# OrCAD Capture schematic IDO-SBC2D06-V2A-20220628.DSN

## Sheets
1 P01 NOTE: title: IDO-SBC2D06-V1; note: NOTE
2 P02 POWER TREE: note: POWER TREE
3 P03 BLOCK: note: BLOCK
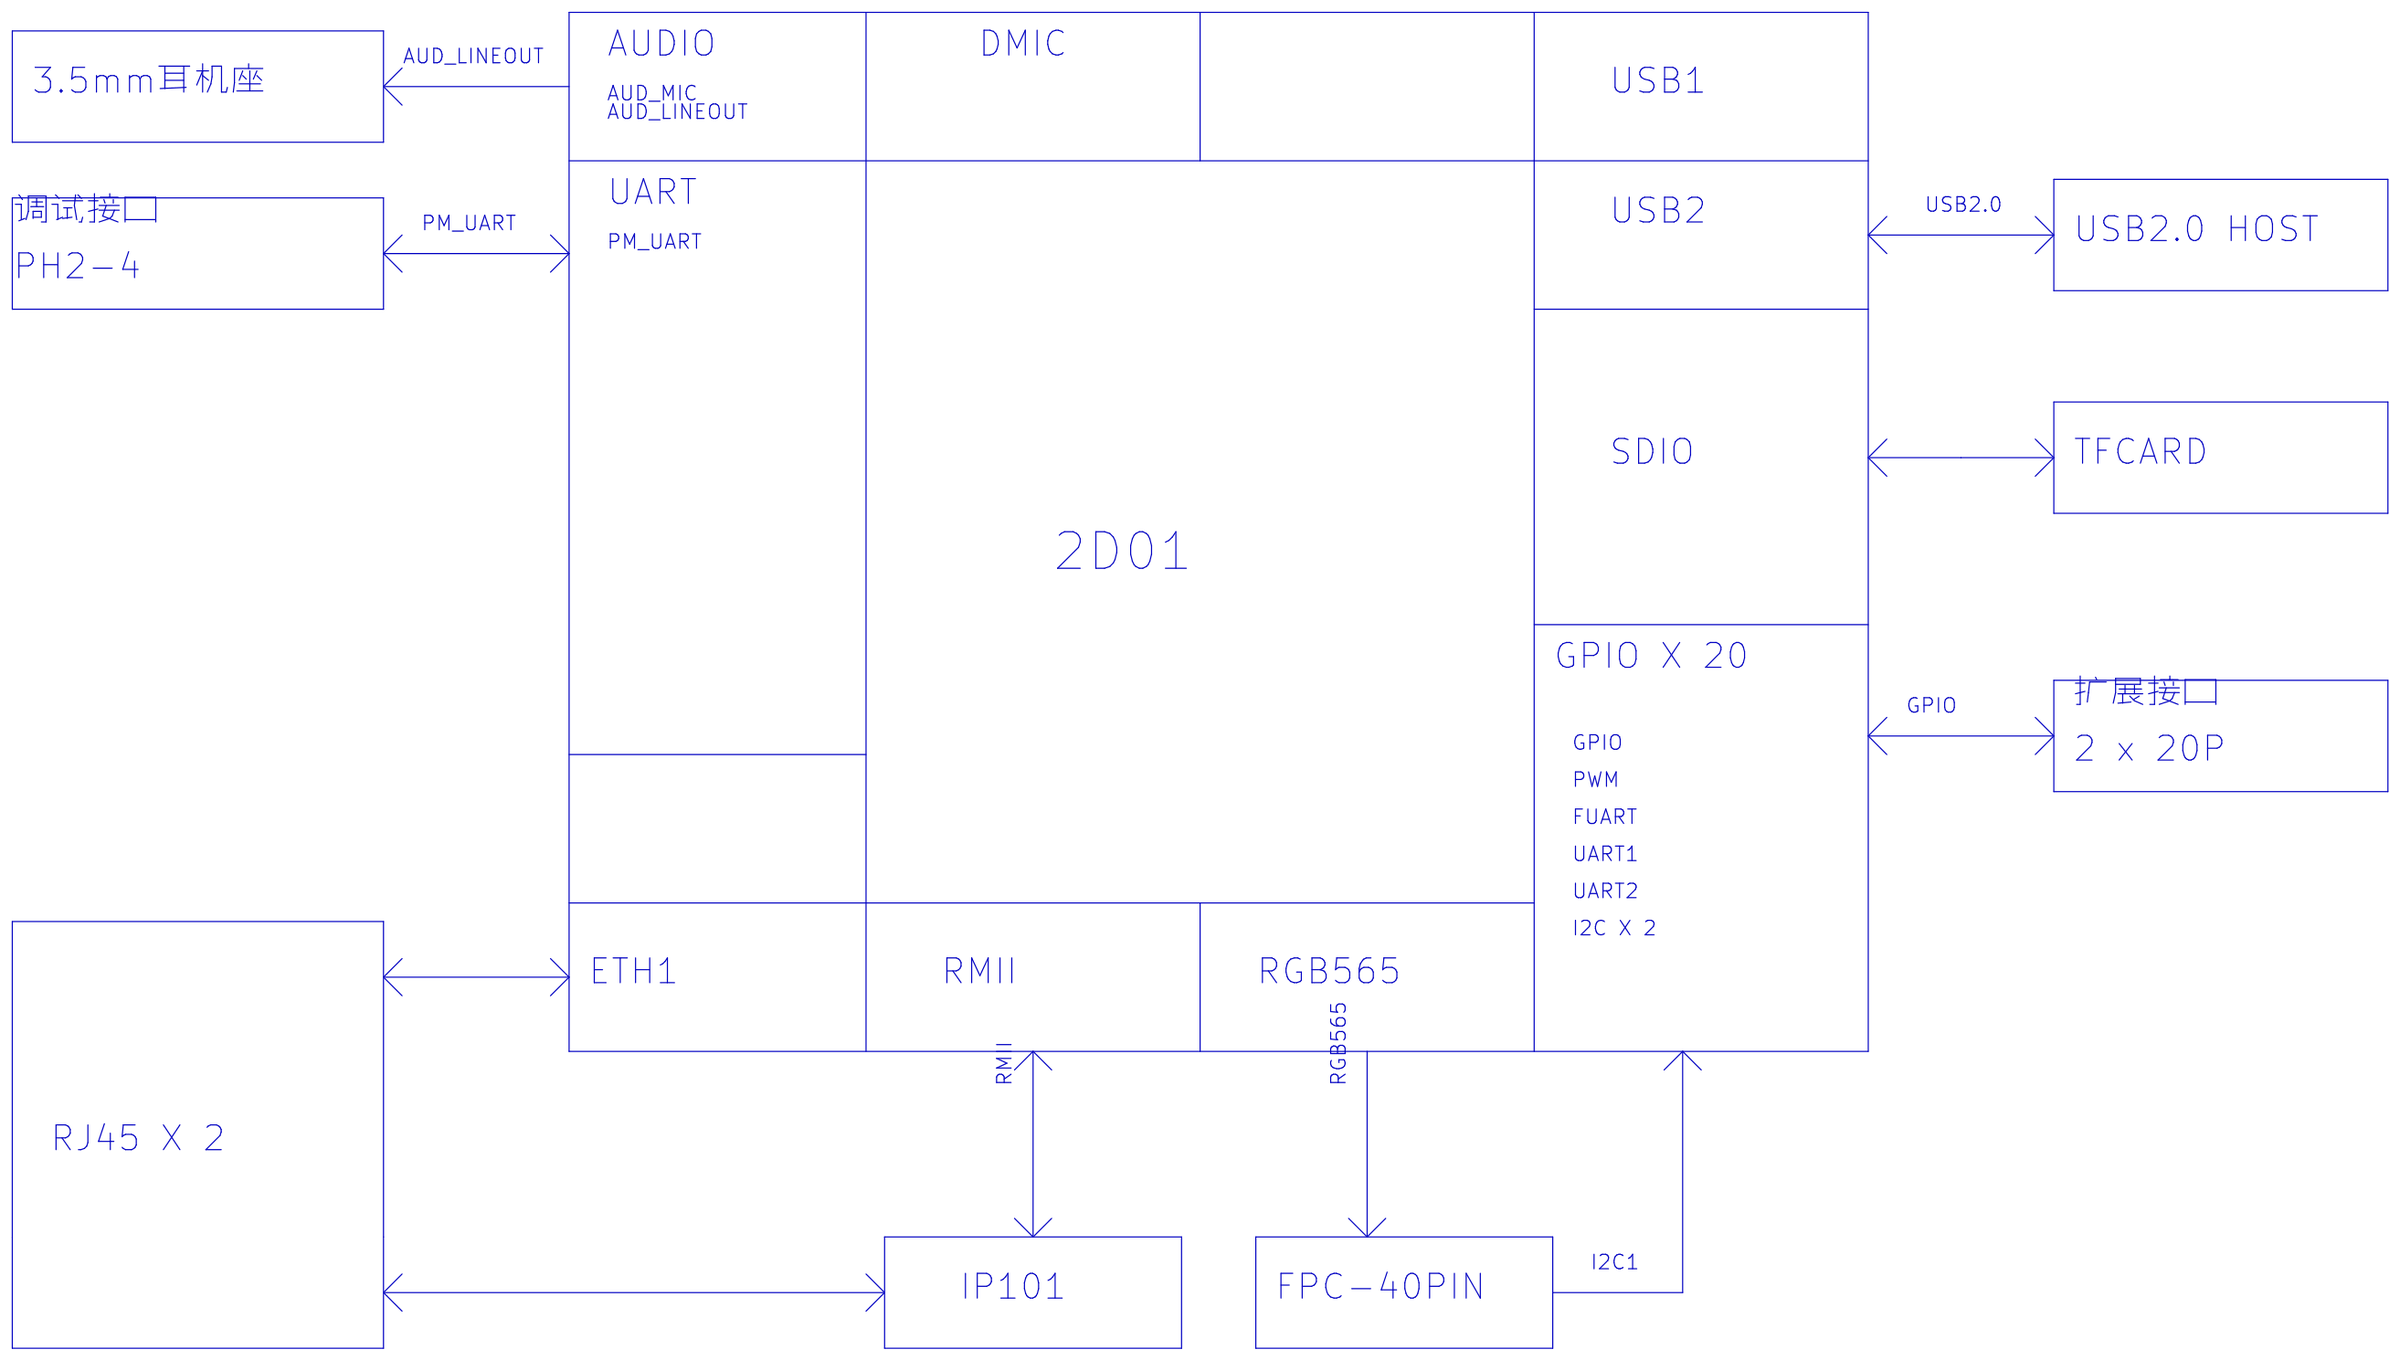
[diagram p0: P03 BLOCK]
4 P04 POWER_SUPPLY: size A3; note: POWER_SUPPLY
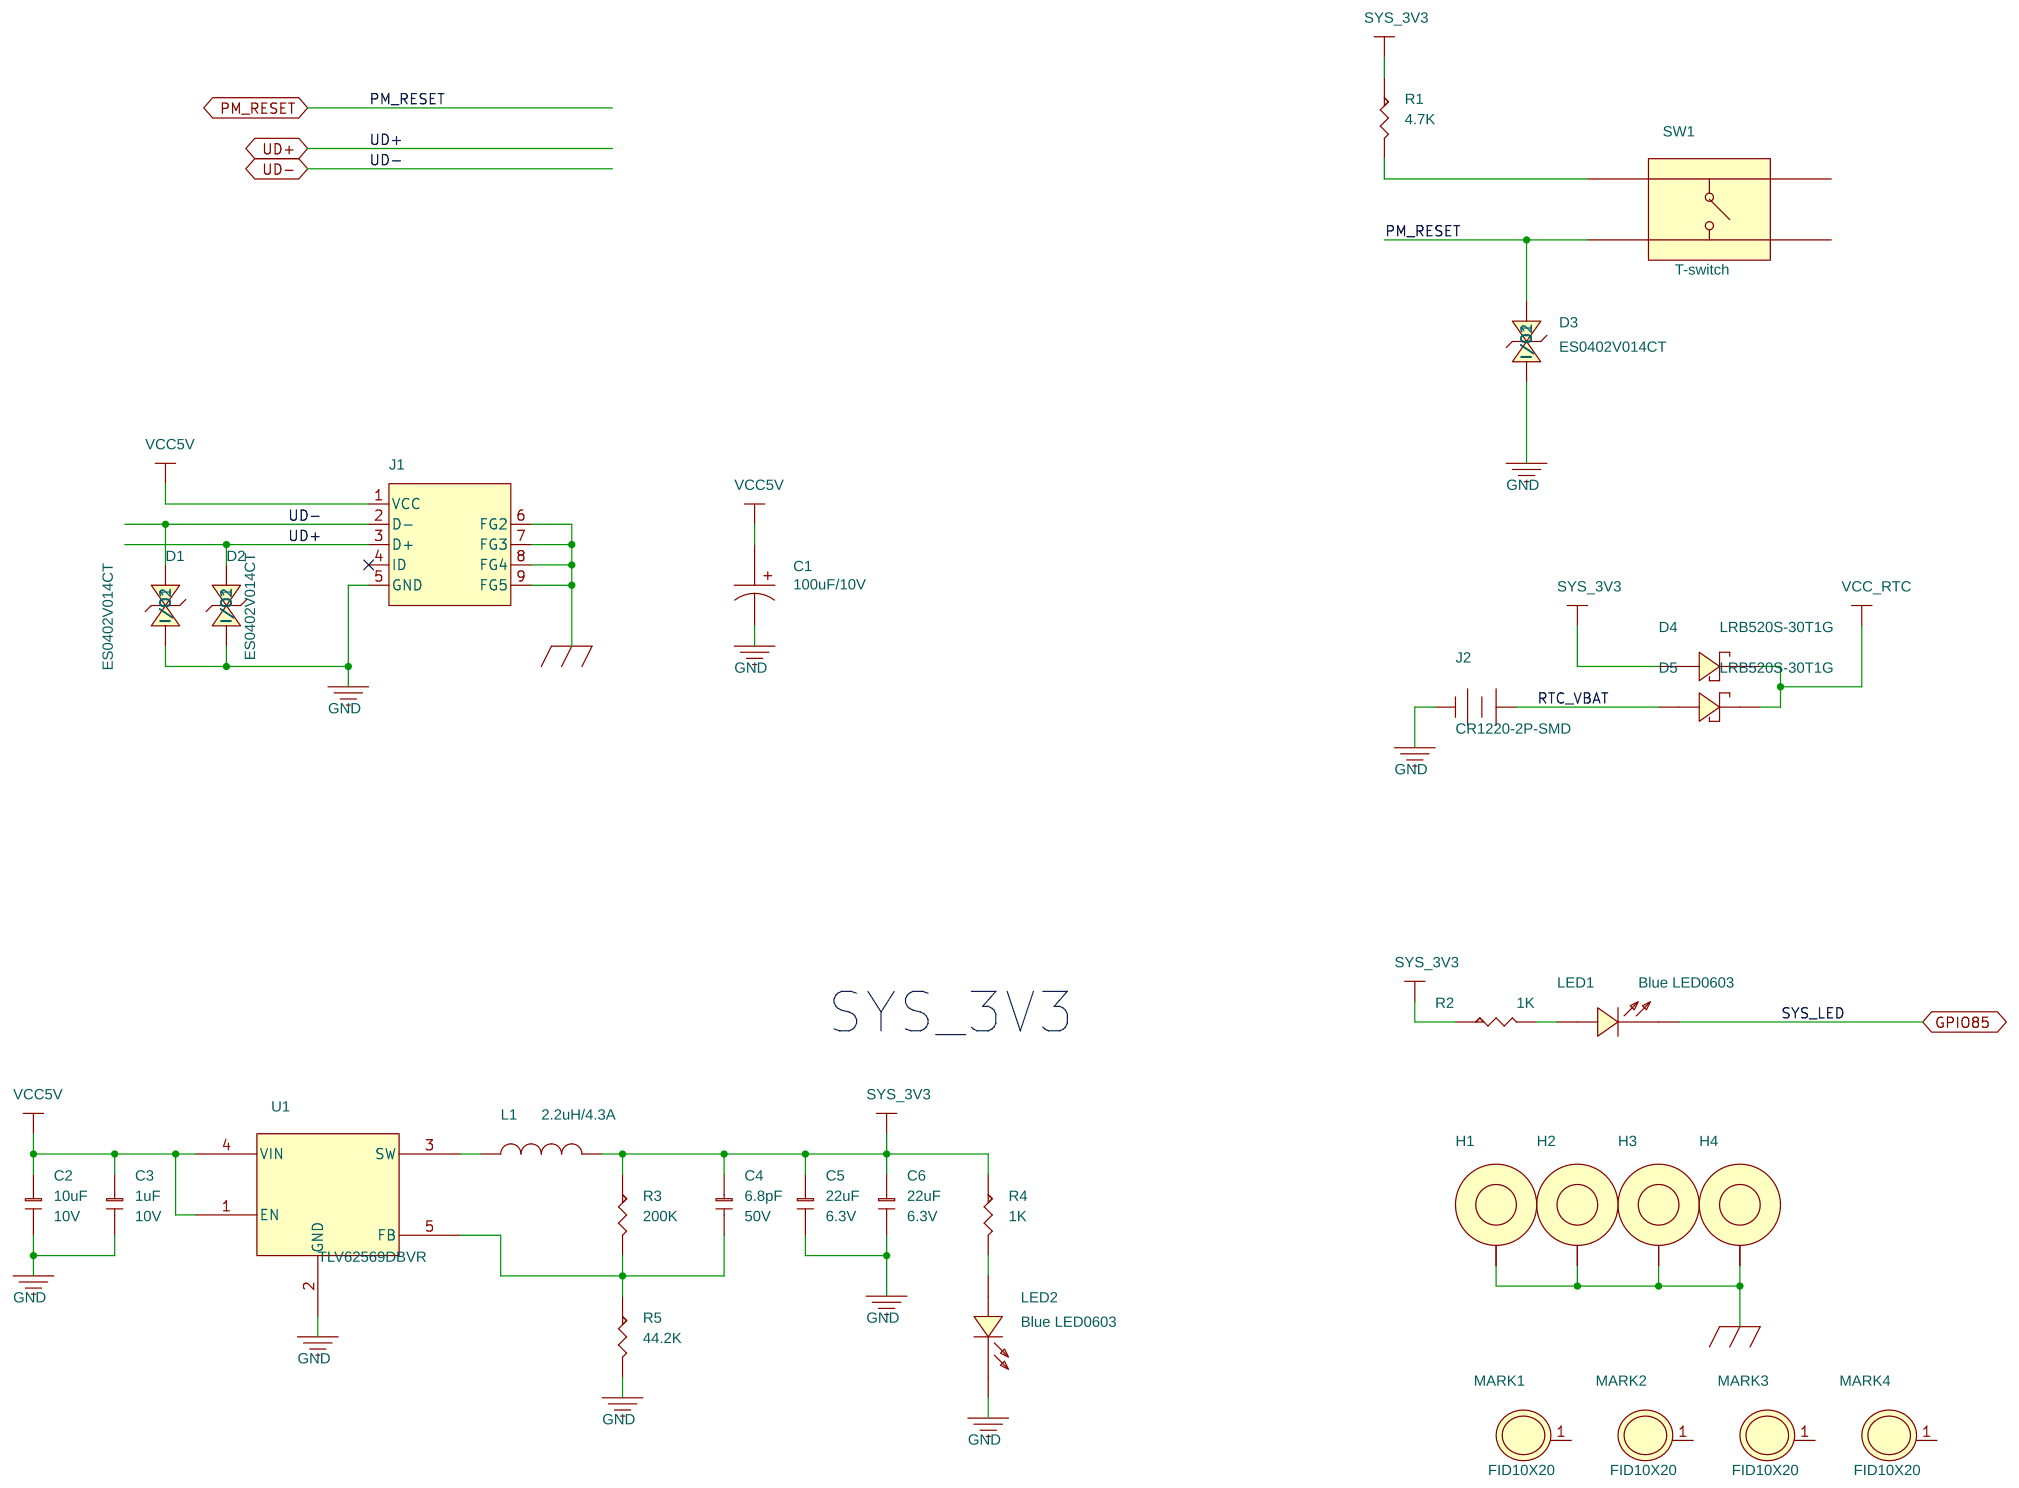
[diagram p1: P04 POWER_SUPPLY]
5 P05 2D02: size A3; note: SSD201
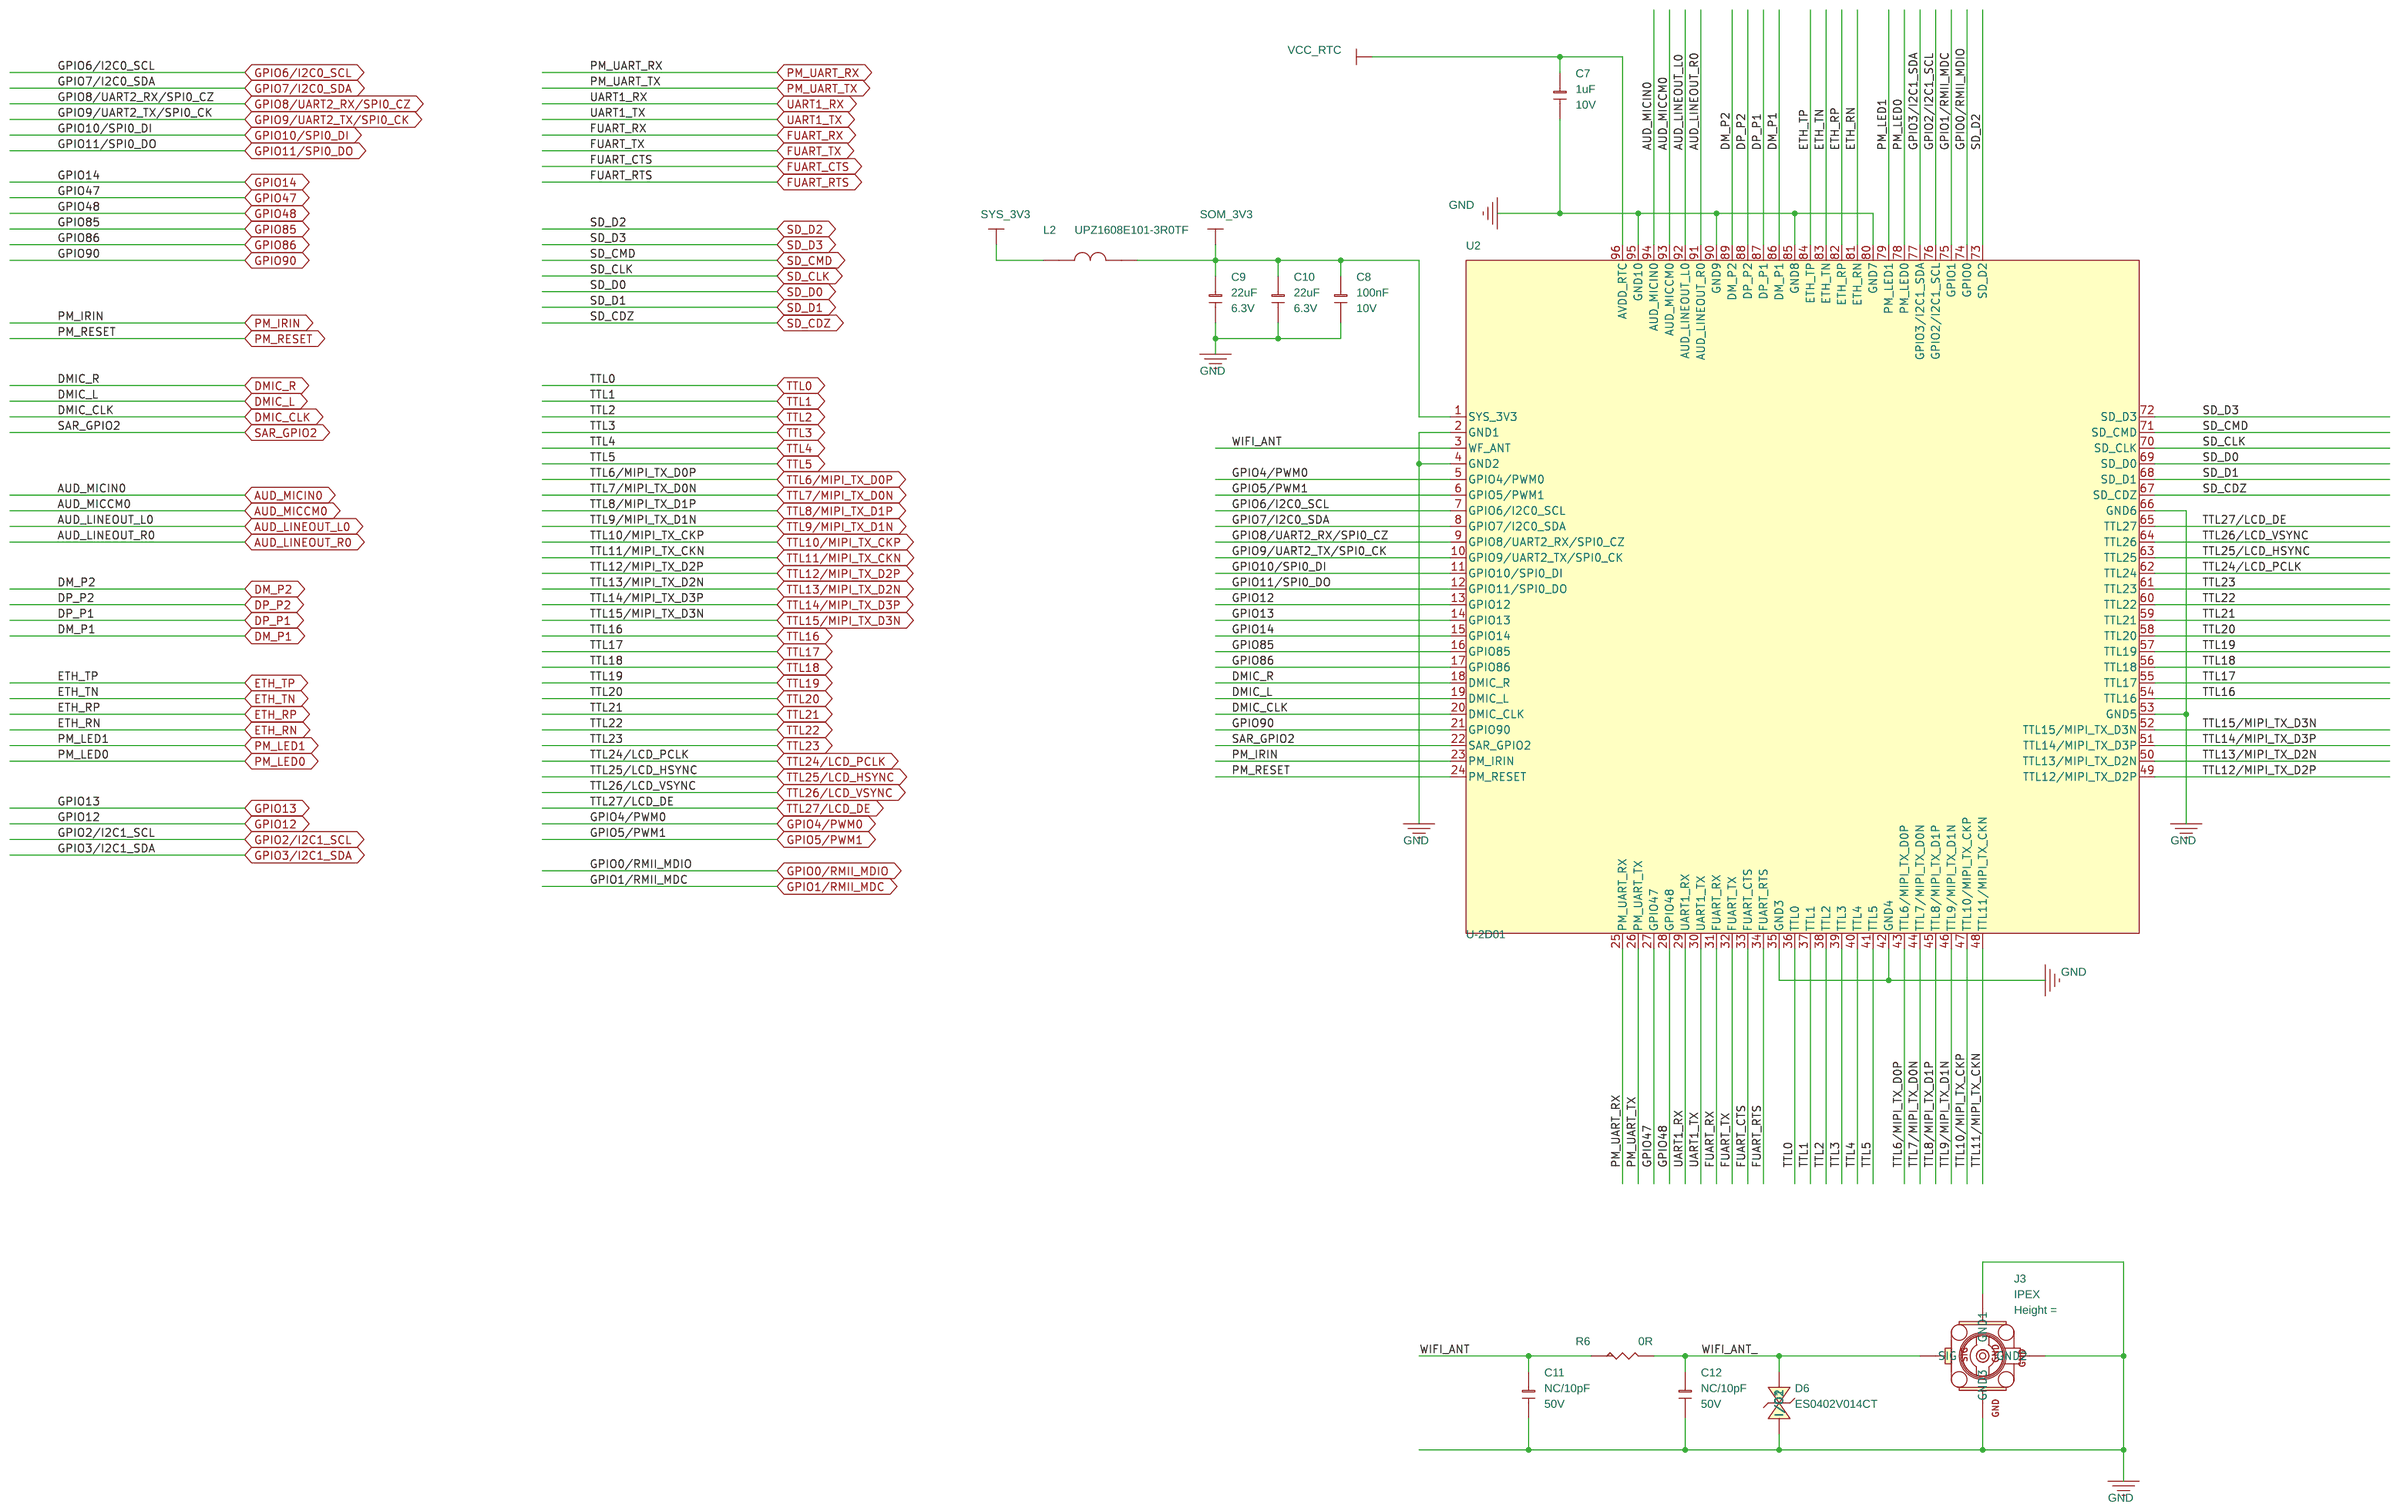
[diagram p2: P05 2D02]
6 P07 ETHERNET: size A3; note: ETHERNET
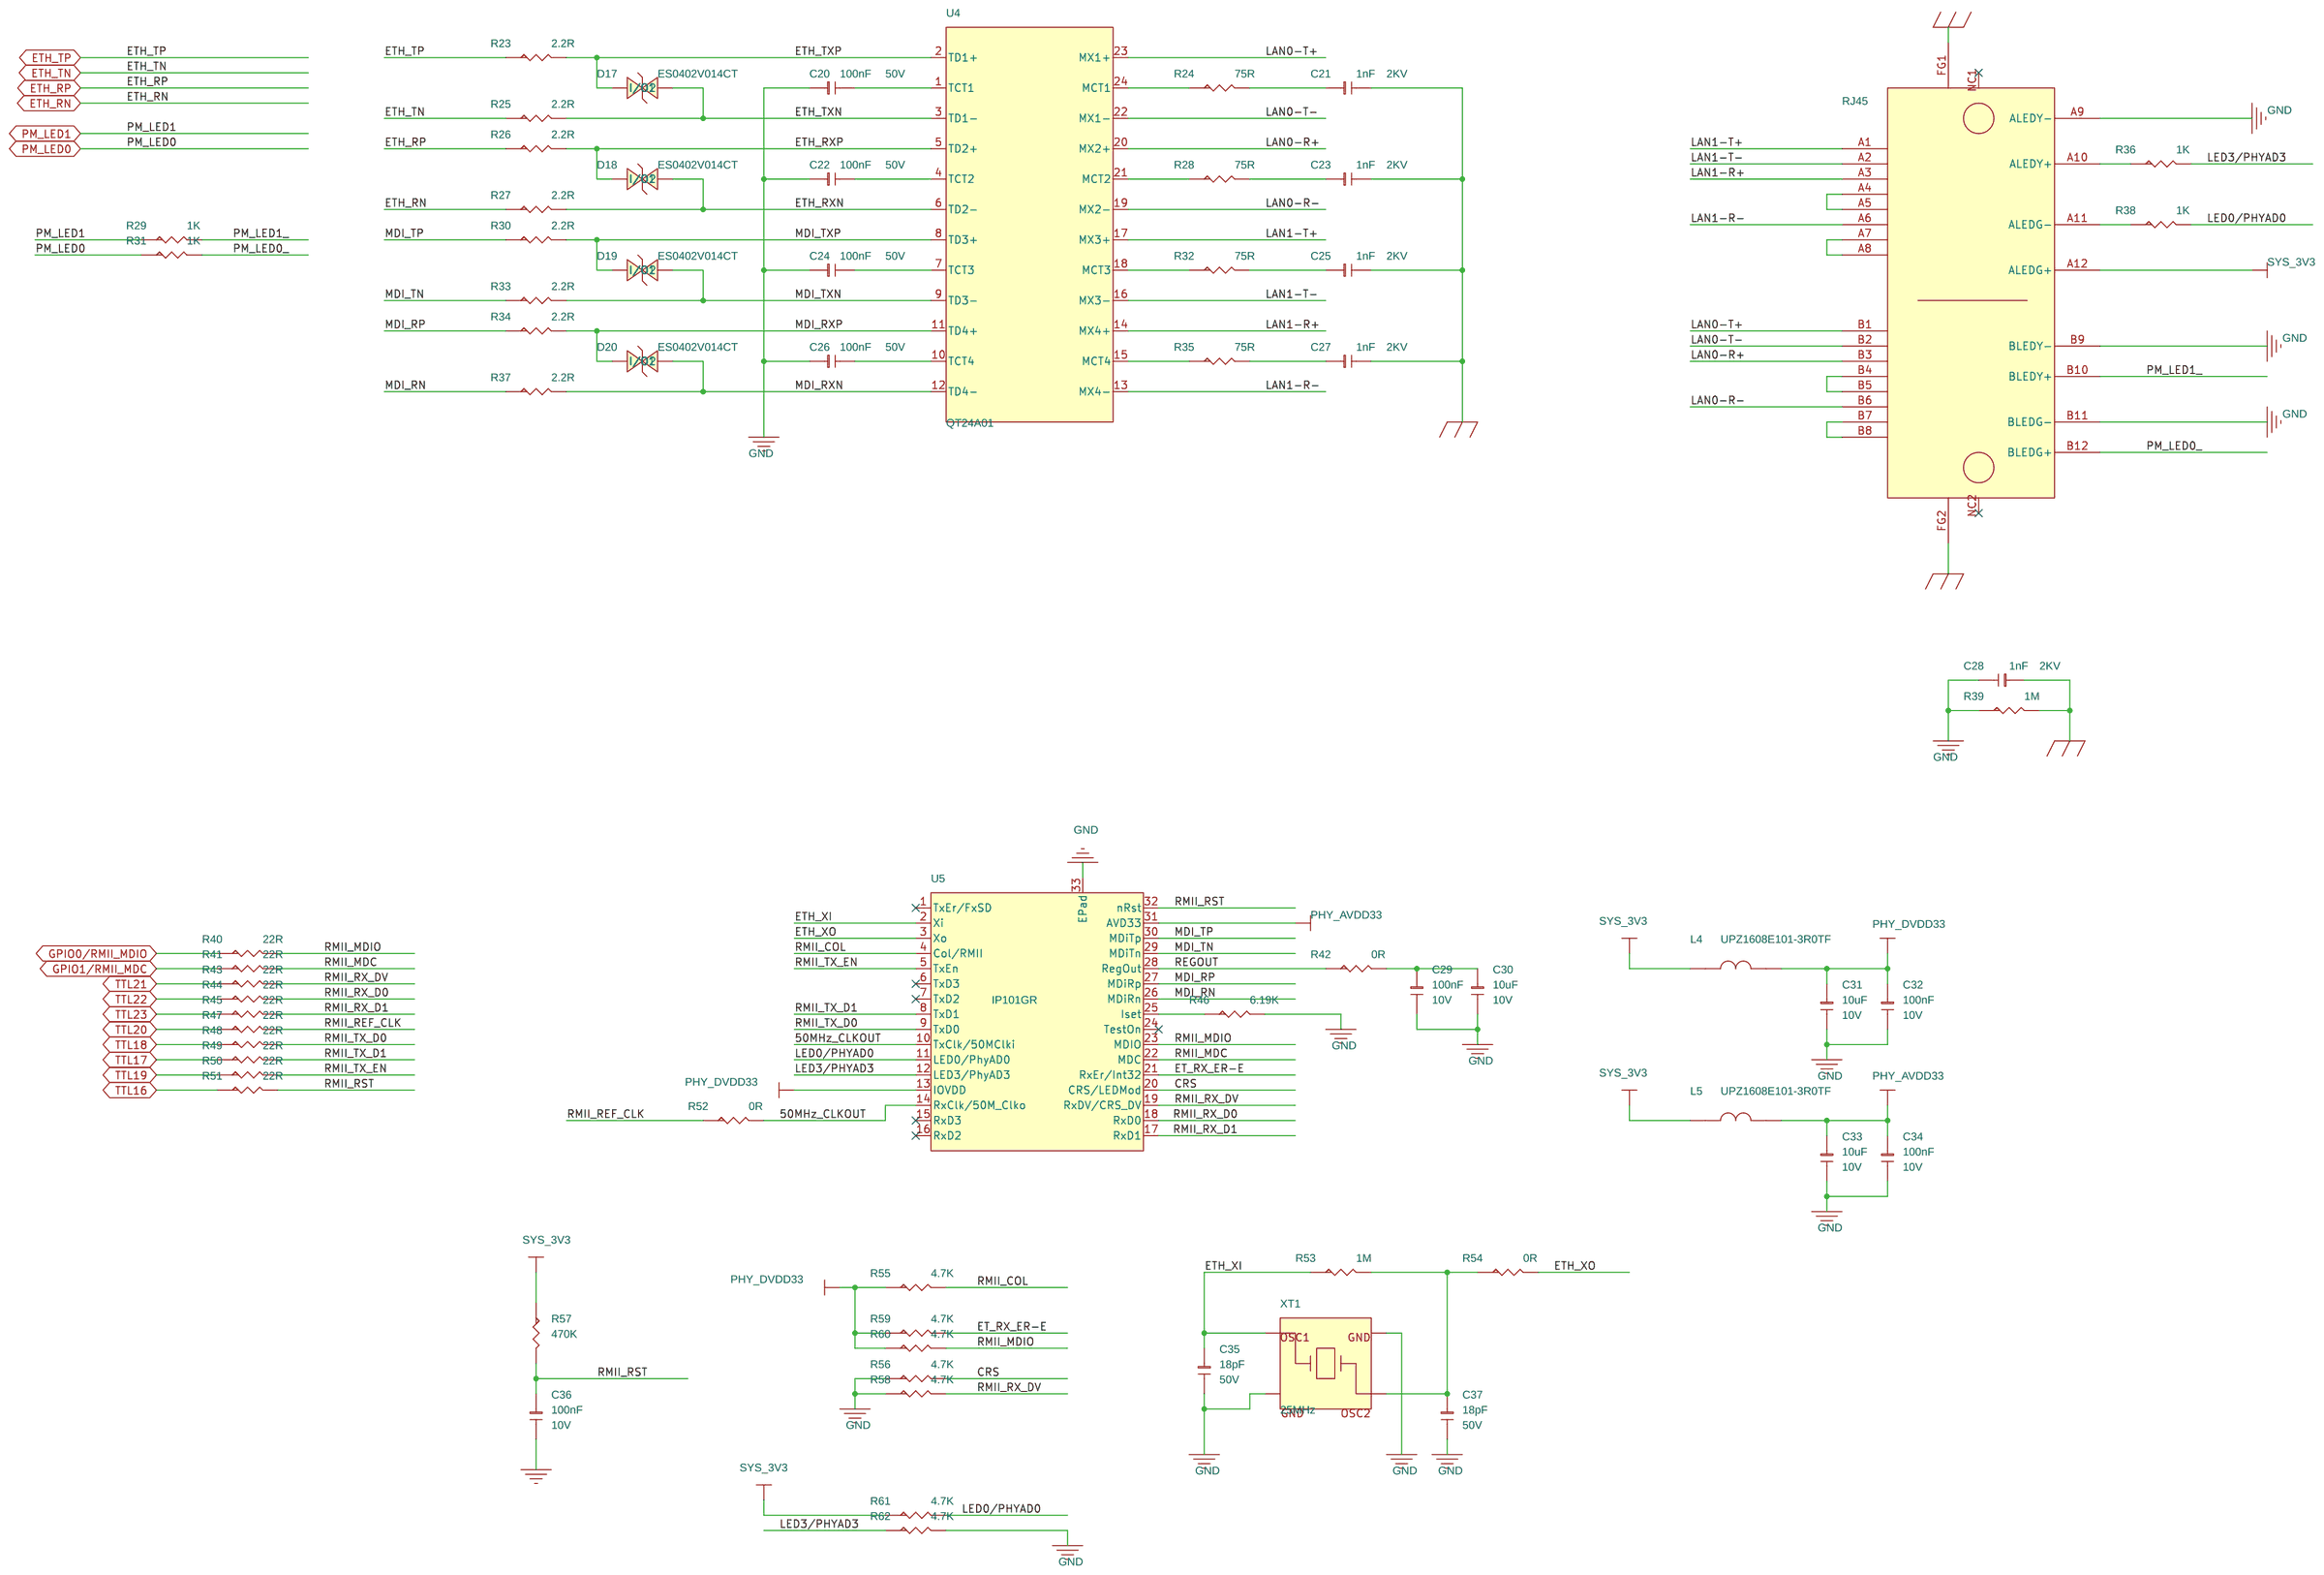
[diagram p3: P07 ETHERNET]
7 P09 AUDIO: size A3; note: AUDIO
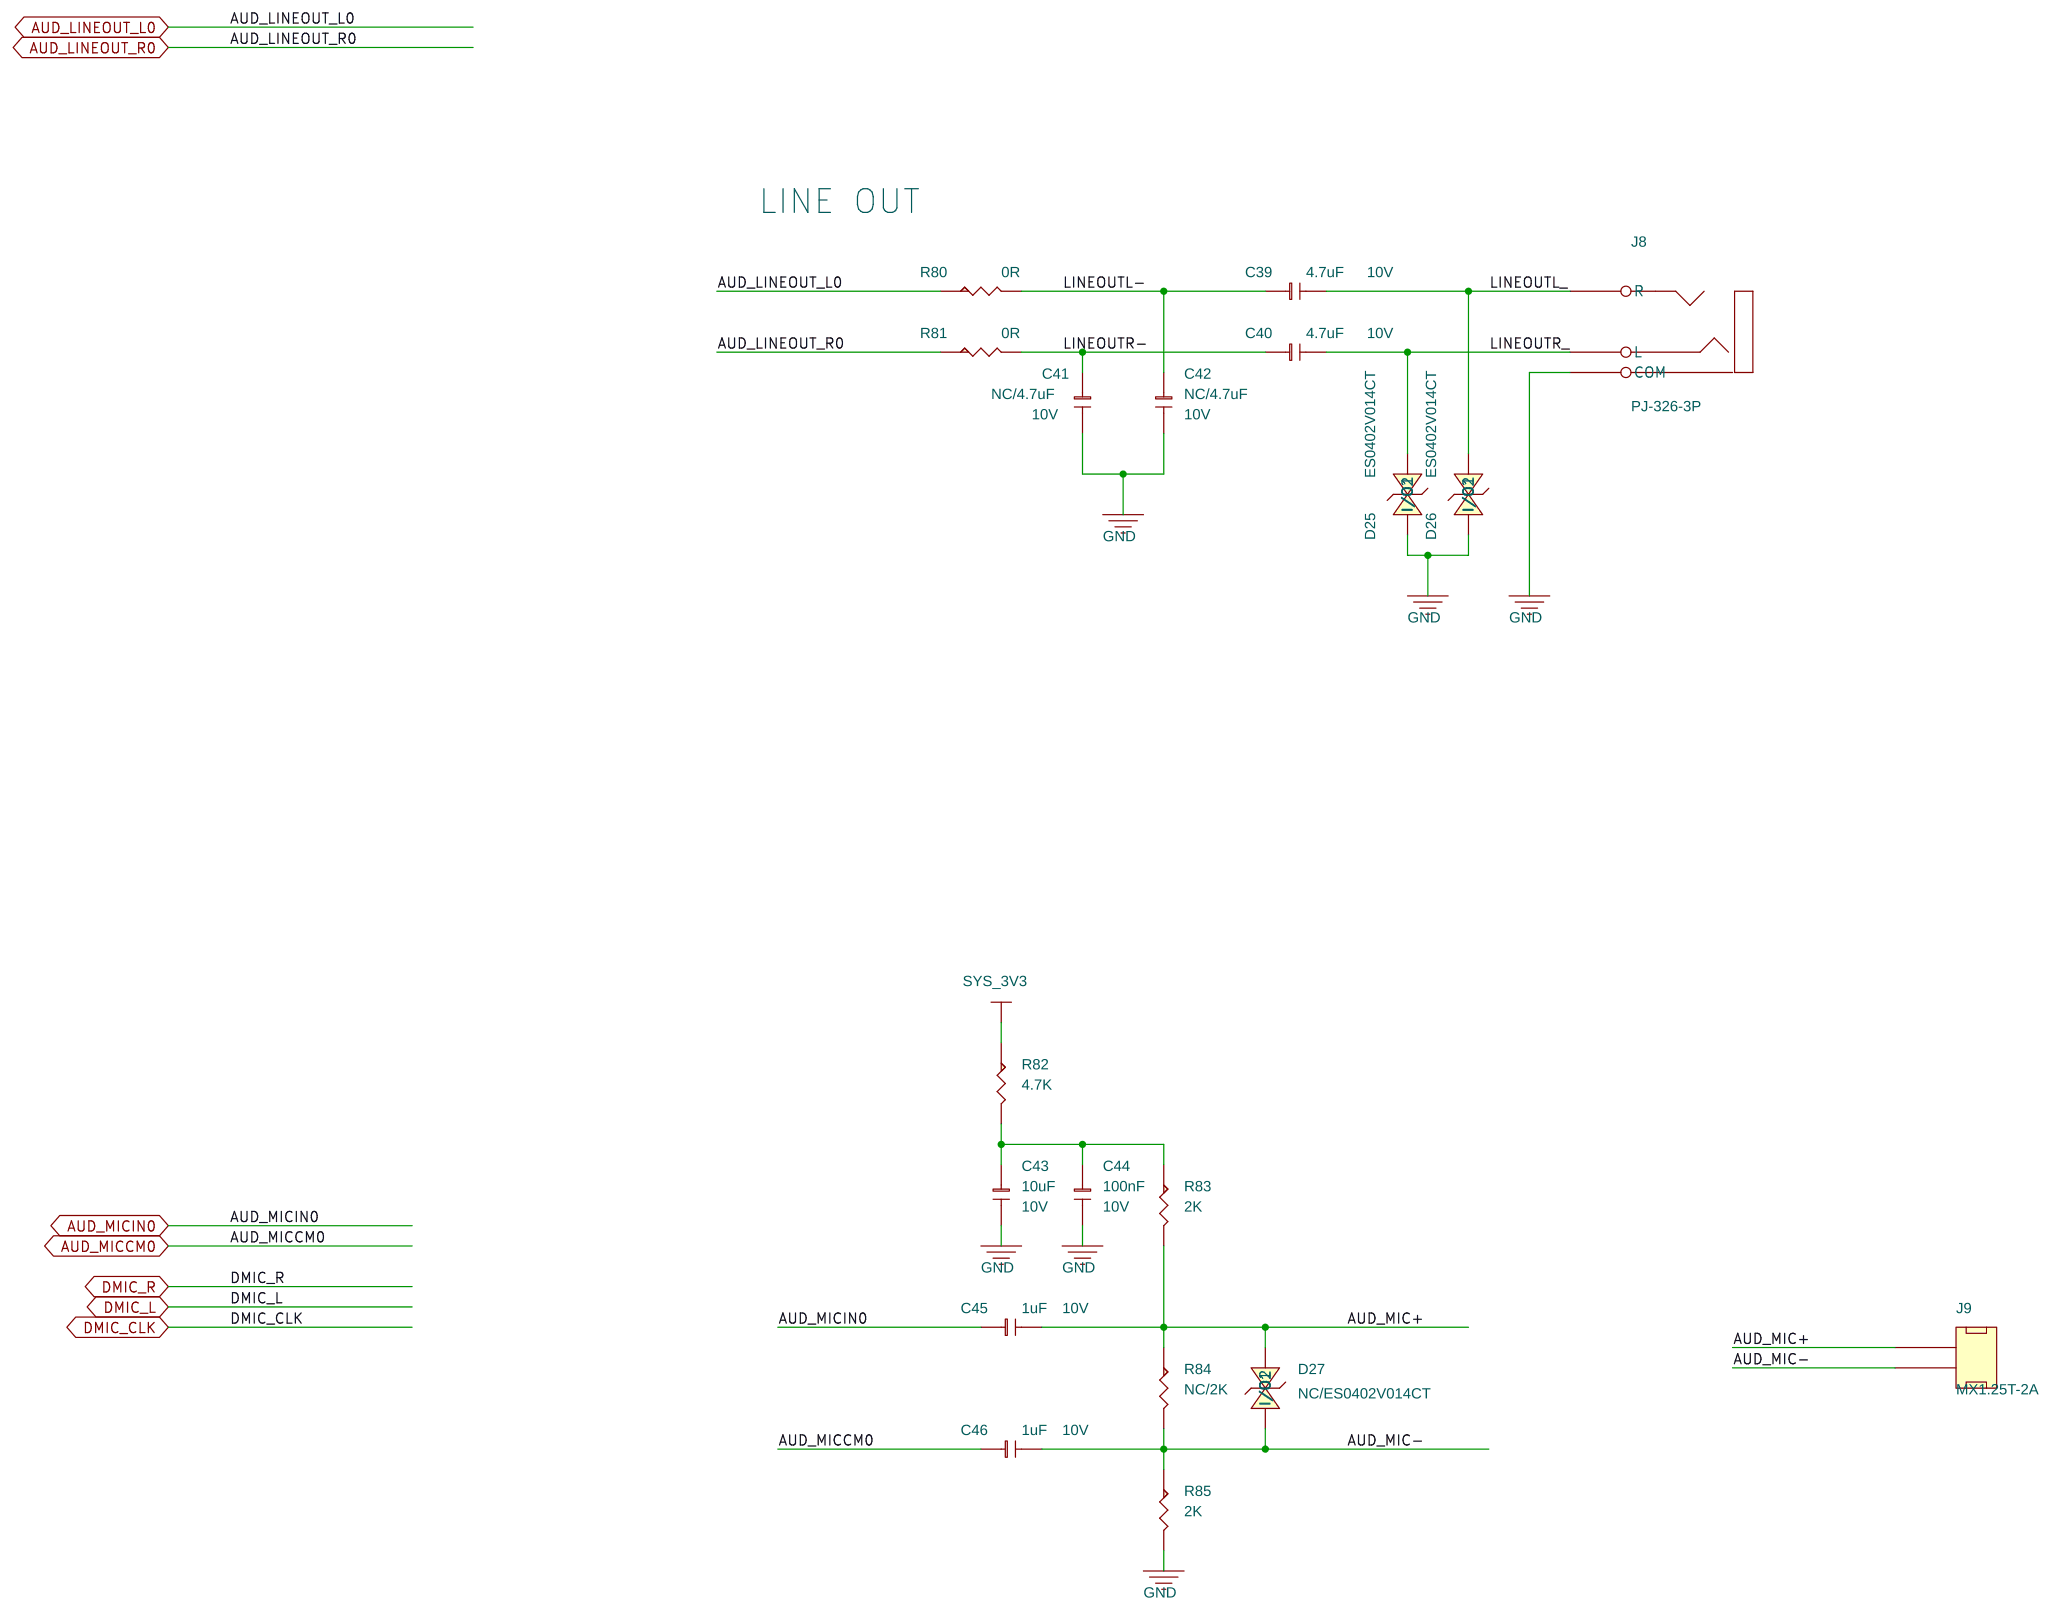
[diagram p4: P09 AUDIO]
8 P08 LCD/TP: size A3; note: LCD/TP
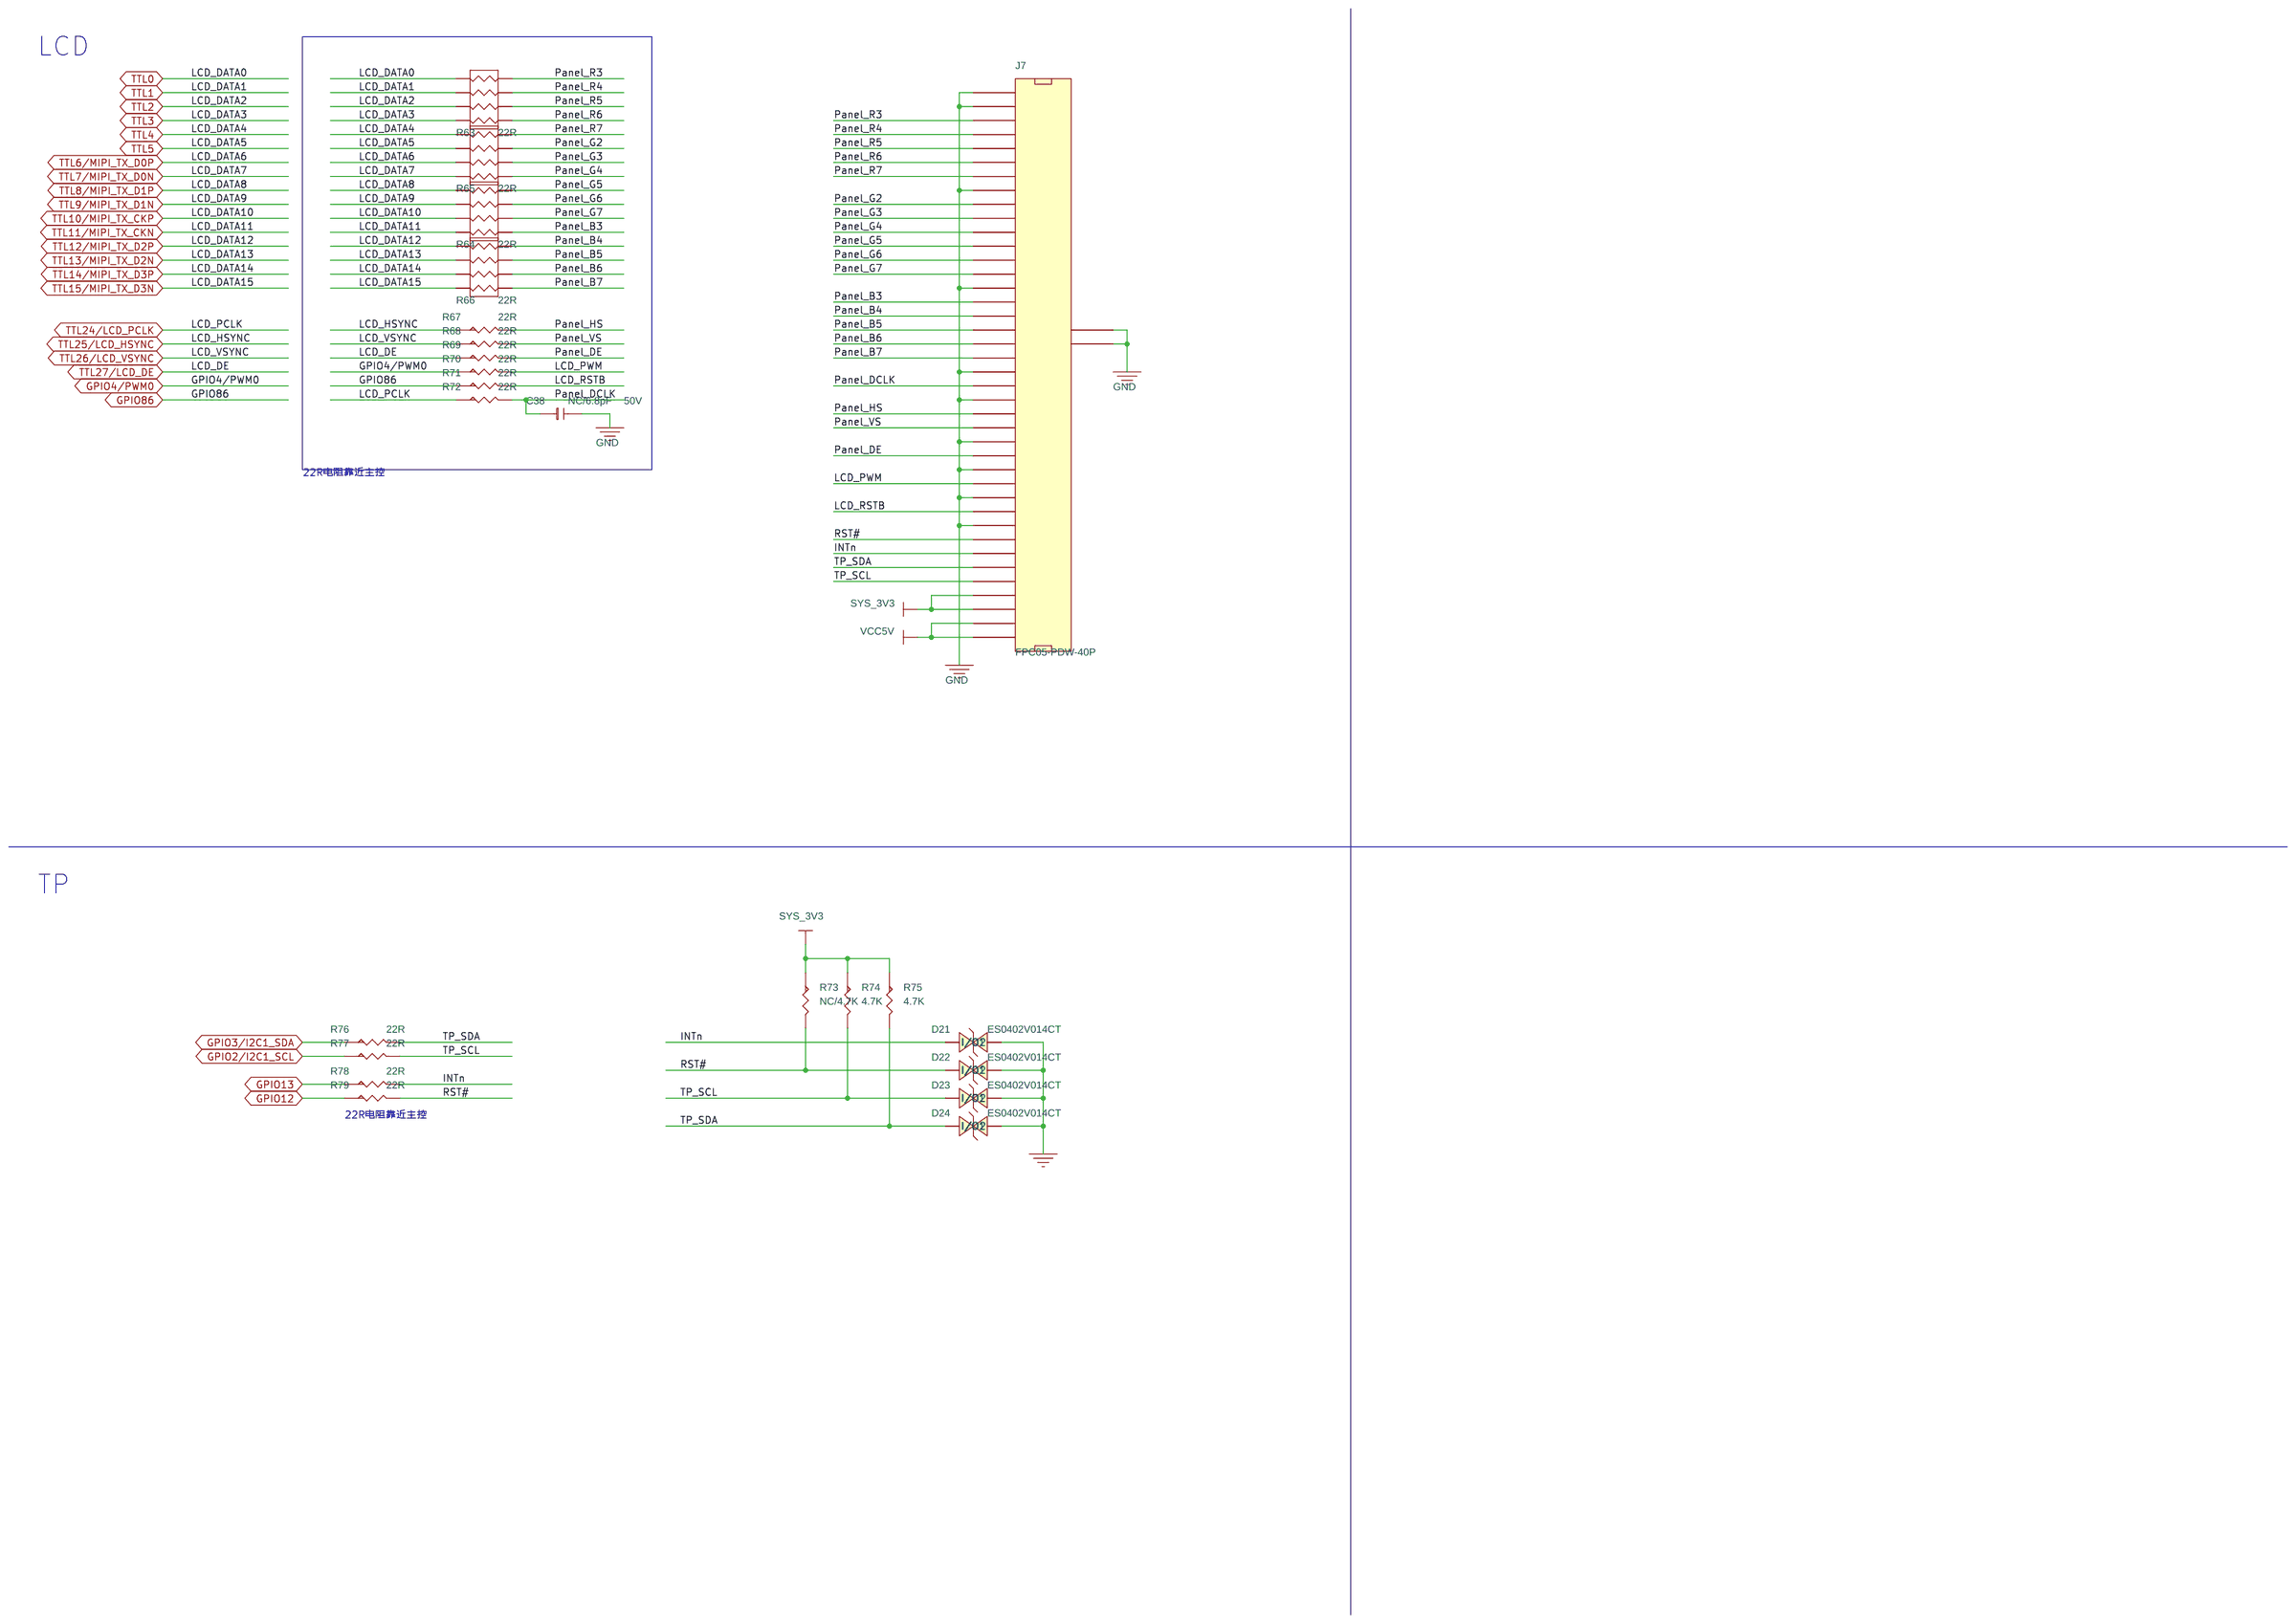
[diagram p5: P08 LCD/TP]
9 P06 USB/SD: size A3; note: USB/SD
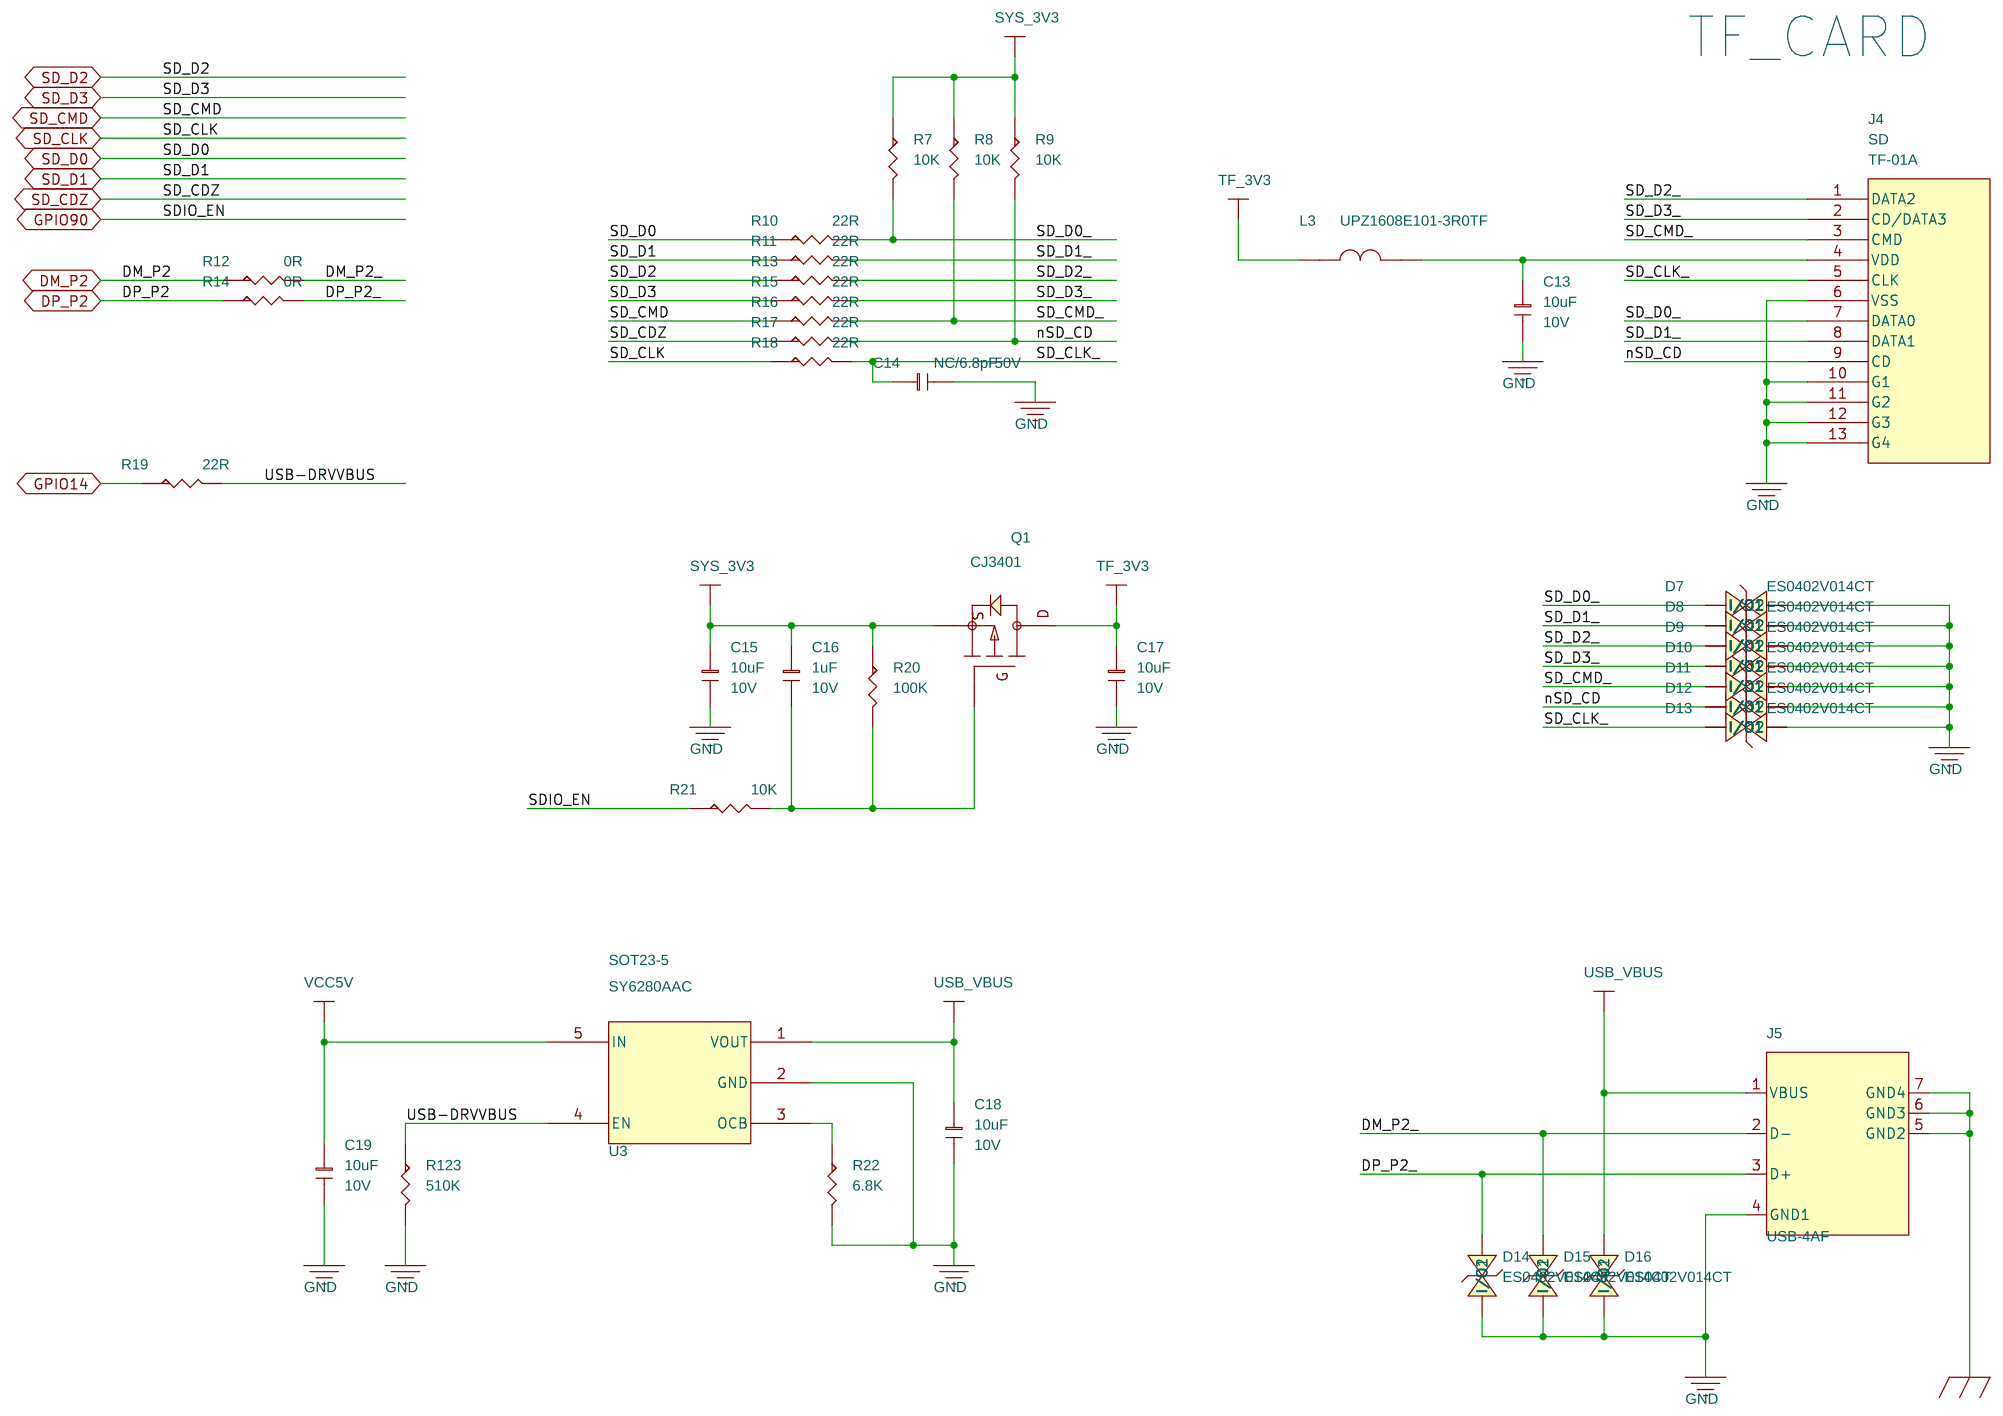
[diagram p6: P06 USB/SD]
10 P10 Debug/RS485/RS232: size A3; note: UART/RS232/RS485
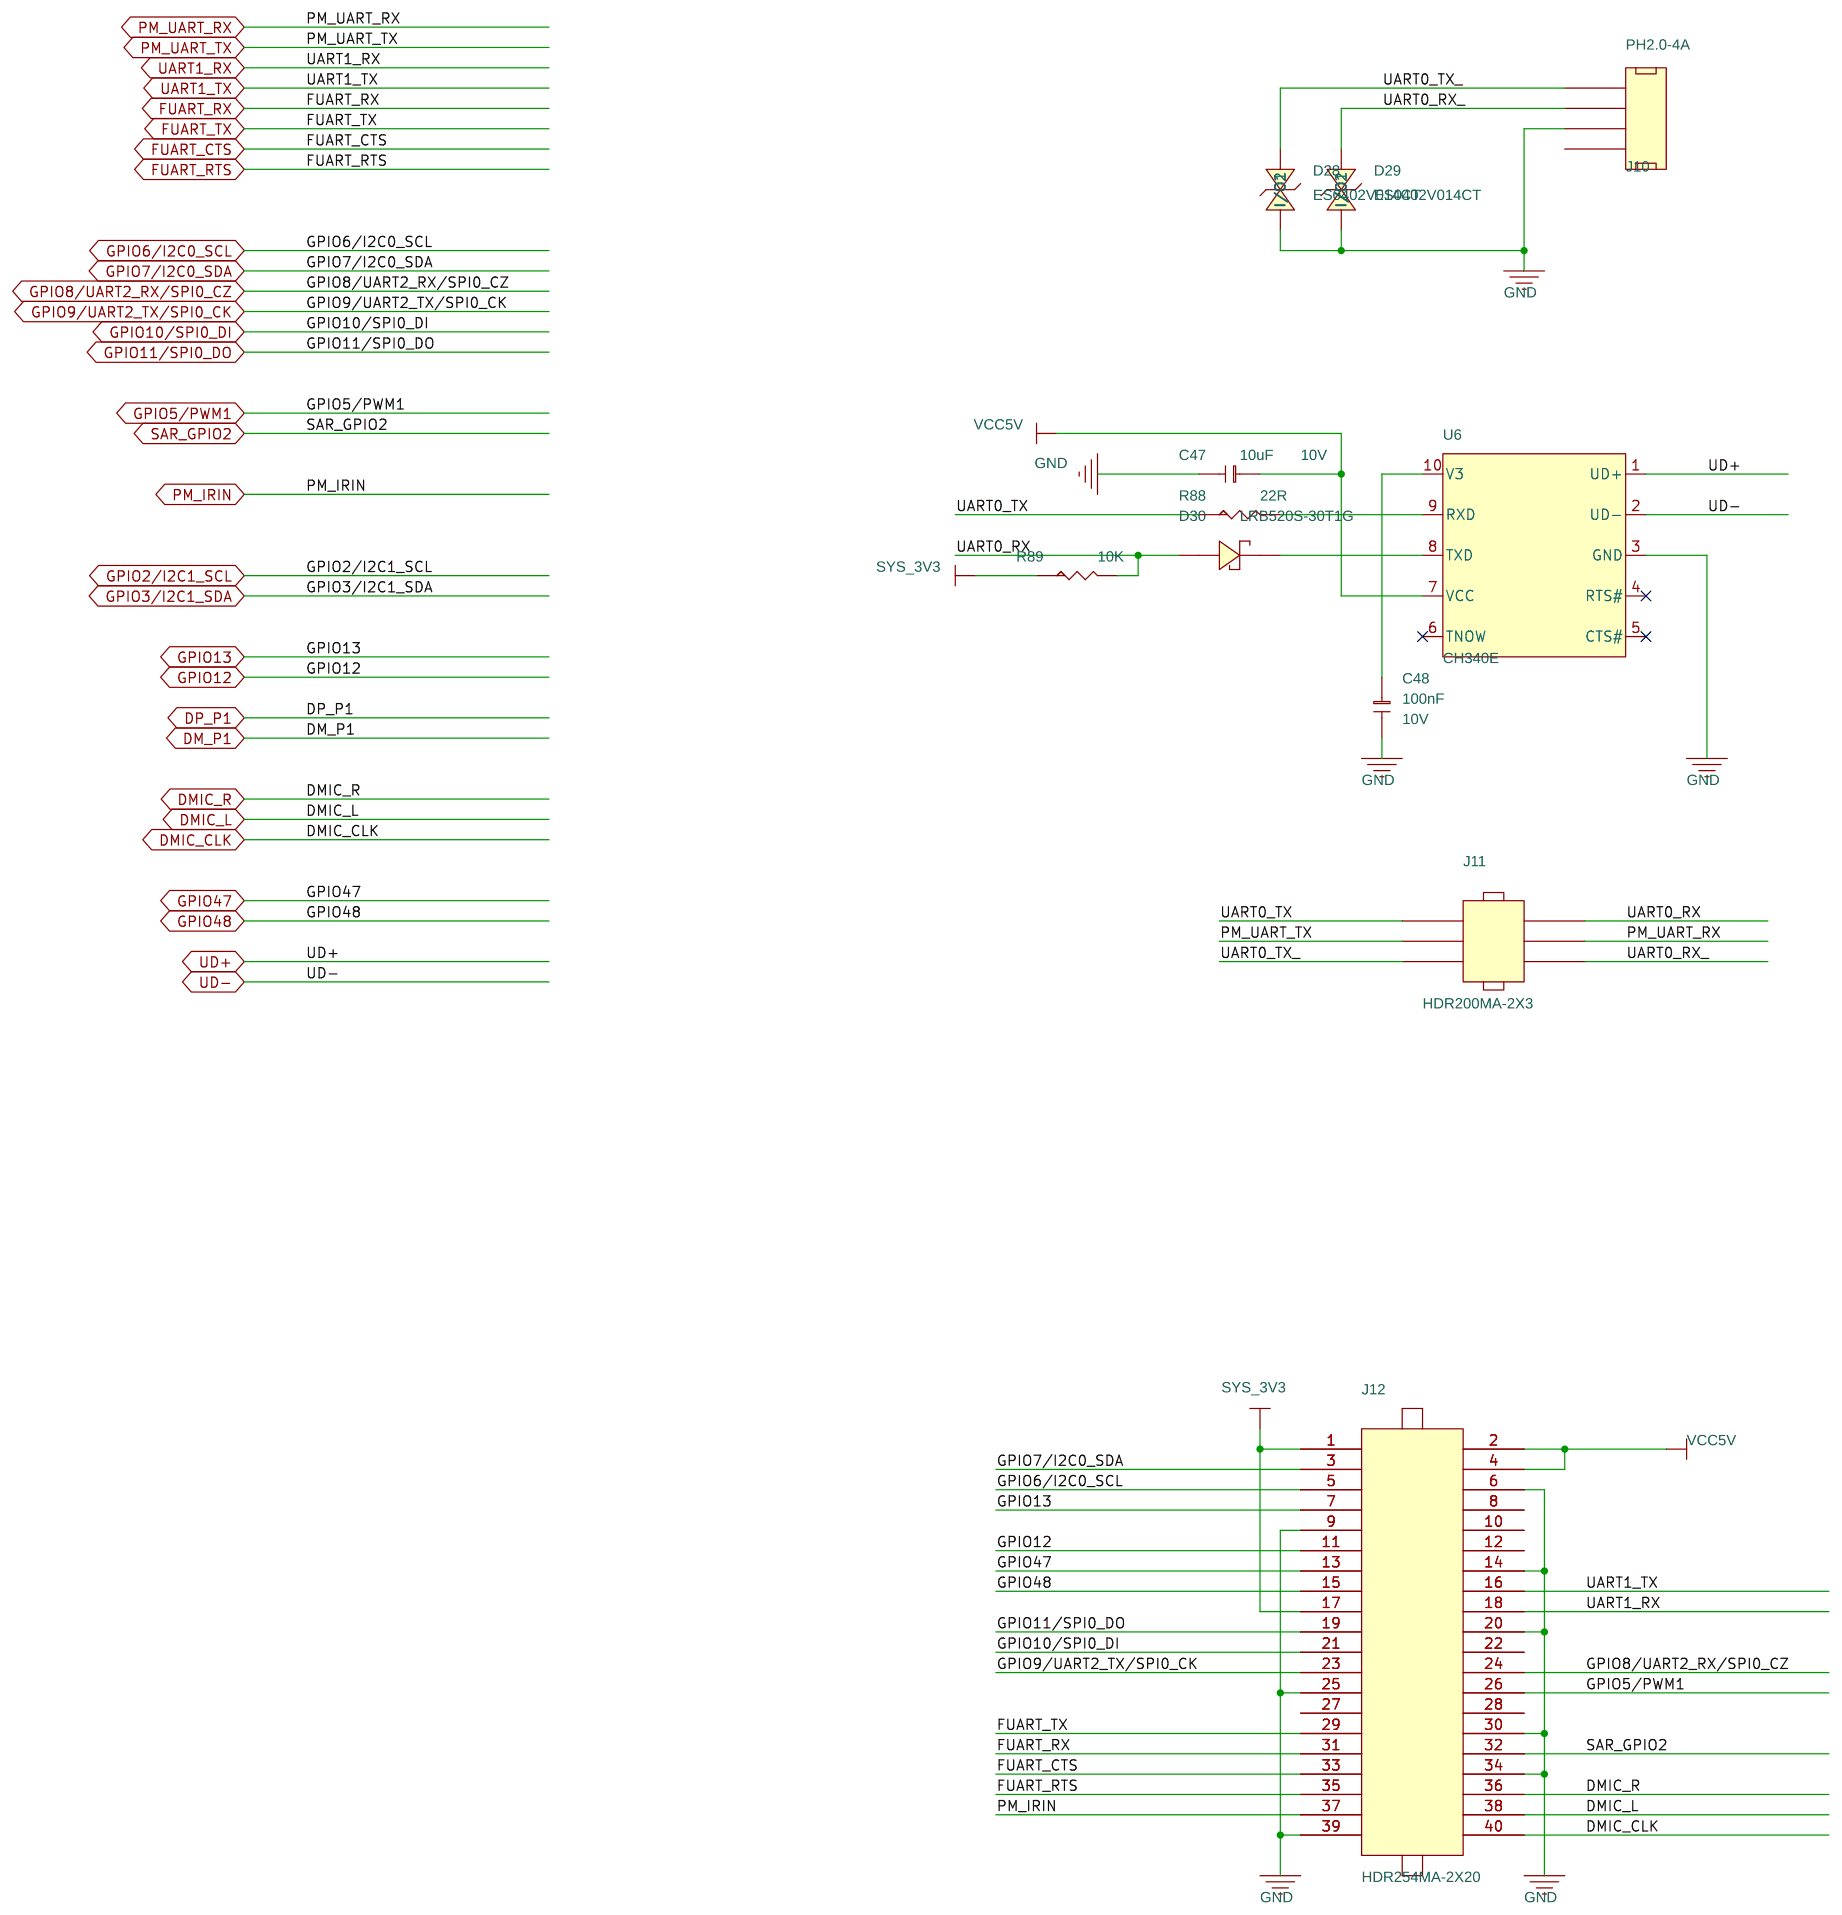
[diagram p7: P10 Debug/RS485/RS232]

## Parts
sheet P04 POWER_SUPPLY
C1  100uF/10V  [CAPAE530X540]
C2  10uF  [C0603L]
C3  1uF  [C0402L]
C4  6.8pF  [C0402L]
C5  22uF  [C0603L]
C6  22uF  [C0603L]
D1  ES0402V014CT  [V0402]
D2  ES0402V014CT  [V0402]
D3  ES0402V014CT  [V0402]
D4  LRB520S-30T1G  [SOD523]
D5  LRB520S-30T1G  [SOD523]
H1  HOLE  [MTG300_600]
H2  HOLE  [MTG300_600]
H3  HOLE  [MTG300_600]
H4  HOLE  [MTG300_600]
J1  MicroUSB  [MICROUSB-5SB]
J2  CR1220-2P-SMD  [CR1220-2P-SMD]
L1  2.2uH/4.3A  [L4040]
LED1  Blue LED0603  [LED0603]
LED2  Blue LED0603  [LED0603]
MARK1  FID10X20  [MARK]
MARK2  FID10X20  [MARK]
MARK3  FID10X20  [MARK]
MARK4  FID10X20  [MARK]
R1  4.7K  [R0402L]
R2  1K  [R0402L]
R3  200K  [R0402L]
R4  1K  [R0402L]
R5  44.2K  [R0402L]
SW1  T-switch  [PB-4P-S-4_5x4_5]
U1  TLV62569DBVR  [SOT23-5]
sheet P05 2D02
C7  1uF  [C0402L]
C8  100nF  [C0402L]
C9  22uF  [C0603L]
C10  22uF  [C0603L]
C11  NC/10pF  [C0402L]
C12  NC/10pF  [C0402L]
D6  ES0402V014CT  [V0402]
J3  IPEX  [IPEX-20279-001E]
L2  UPZ1608E101-3R0TF  [L0603]
R6  0R  [R0402L]
U2  U-2D01  [IDO_2D01_LGA96]
sheet P06 USB/SD
C13  10uF  [C0603L]
C14  NC/6.8pF  [C0402L]
C15  10uF  [C0603L]
C16  1uF  [C0402L]
C17  10uF  [C0603L]
C18  10uF  [C0603L]
C19  10uF  [C0603L]
D7  ES0402V014CT  [V0402]
D8  ES0402V014CT  [V0402]
D9  ES0402V014CT  [V0402]
D10  ES0402V014CT  [V0402]
D11  ES0402V014CT  [V0402]
D12  ES0402V014CT  [V0402]
D13  ES0402V014CT  [V0402]
D14  ES0402V014CT  [V0402]
D15  ES0402V014CT  [V0402]
D16  ES0402V014CT  [V0402]
J4  SD  [TF-01A]
J5  USB-4AF  [USB-4AF-DIP-3W]
L3  UPZ1608E101-3R0TF  [L0603]
Q1  CJ3401  [SOT23]
R7  10K  [R0402L]
R8  10K  [R0402L]
R9  10K  [R0402L]
R10  22R  [R0402L]
R11  22R  [R0402L]
R12  0R  [R0402L]
R13  22R  [R0402L]
R14  0R  [R0402L]
R15  22R  [R0402L]
R16  22R  [R0402L]
R17  22R  [R0402L]
R18  22R  [R0402L]
R19  22R  [R0402L]
R20  100K  [R0402L]
R21  10K  [R0402L]
R22  6.8K  [R0402L]
R123  510K  [R0402L]
U3  SY6280AAC  [SOT23-5]
sheet P07 ETHERNET
C20  100nF  [C0402L]
C21  1nF  [C1206L]
C22  100nF  [C0402L]
C23  1nF  [C1206L]
C24  100nF  [C0402L]
C25  1nF  [C1206L]
C26  100nF  [C0402L]
C27  1nF  [C1206L]
C28  1nF  [C1206L]
C29  100nF  [C0402L]
C30  10uF  [C0603L]
C31  10uF  [C0603L]
C32  100nF  [C0402L]
C33  10uF  [C0603L]
C34  100nF  [C0402L]
C35  18pF  [C0402L]
C36  100nF  [C0402L]
C37  18pF  [C0402L]
D17  ES0402V014CT  [V0402]
D18  ES0402V014CT  [V0402]
D19  ES0402V014CT  [V0402]
D20  ES0402V014CT  [V0402]
J6  RJ45  [RJ45-1X2-8P8C-R-LED]
L4  UPZ1608E101-3R0TF  [L0603]
L5  UPZ1608E101-3R0TF  [L0603]
R23  2.2R  [R0402L]
R24  75R  [R0603L]
R25  2.2R  [R0402L]
R26  2.2R  [R0402L]
R27  2.2R  [R0402L]
R28  75R  [R0603L]
R29  1K  [R0402L]
R30  2.2R  [R0402L]
R31  1K  [R0402L]
R32  75R  [R0603L]
R33  2.2R  [R0402L]
R34  2.2R  [R0402L]
R35  75R  [R0603L]
R36  1K  [R0402L]
R37  2.2R  [R0402L]
R38  1K  [R0402L]
R39  1M  [R0805L]
R40  22R  [R0402L]
R41  22R  [R0402L]
R42  0R  [R0402L]
R43  22R  [R0402L]
R44  22R  [R0402L]
R45  22R  [R0402L]
R46  6.19K  [R0402L]
R47  22R  [R0402L]
R48  22R  [R0402L]
R49  22R  [R0402L]
R50  22R  [R0402L]
R51  22R  [R0402L]
R52  0R  [R0402L]
R53  1M  [R0402L]
R54  0R  [R0402L]
R55  4.7K  [R0402L]
R56  4.7K  [R0402L]
R57  470K  [R0402L]
R58  4.7K  [R0402L]
R59  4.7K  [R0402L]
R60  4.7K  [R0402L]
R61  4.7K  [R0402L]
R62  4.7K  [R0402L]
U4  QT24A01  [QT24A01-SOP24]
U5  IP101GR  [IP101GR-VQFN-32]
XT1  25MHz  [xtal_32x25_4p]
sheet P08 LCD/TP
C38  NC/6.8pF  [C0402L]
D21  ES0402V014CT  [V0402]
D22  ES0402V014CT  [V0402]
D23  ES0402V014CT  [V0402]
D24  ES0402V014CT  [V0402]
J7  FPC05-PDW-40P  [FPC05-PDW-40P]
R63  22R  [RN_0402X4]
R64  22R  [RN_0402X4]
R65  22R  [RN_0402X4]
R66  22R  [RN_0402X4]
R67  22R  [R0402L]
R68  22R  [R0402L]
R69  22R  [R0402L]
R70  22R  [R0402L]
R71  22R  [R0402L]
R72  22R  [R0402L]
R73  NC/4.7K  [R0402L]
R74  4.7K  [R0402L]
R75  4.7K  [R0402L]
R76  22R  [R0402L]
R77  22R  [R0402L]
R78  22R  [R0402L]
R79  22R  [R0402L]
sheet P09 AUDIO
C39  4.7uF  [C0402L]
C40  4.7uF  [C0402L]
C41  NC/4.7uF  [C0402L]
C42  NC/4.7uF  [C0402L]
C43  10uF  [C0603L]
C44  100nF  [C0402L]
C45  1uF  [C0402L]
C46  1uF  [C0402L]
D25  ES0402V014CT  [V0402]
D26  ES0402V014CT  [V0402]
D27  NC/ES0402V014CT  [V0402]
J8  PJ-326-3P  [PJ-326A-3P]
J9  MX1.25T-2A  [MX125T-2A]
R80  0R  [R0402L]
R81  0R  [R0402L]
R82  4.7K  [R0402L]
R83  2K  [R0402L]
R84  NC/2K  [R0402L]
R85  2K  [R0402L]
sheet P10 Debug/RS485/RS232
C47  10uF  [C0603L]
C48  100nF  [C0402L]
D28  ES0402V014CT  [V0402]
D29  ES0402V014CT  [V0402]
D30  LRB520S-30T1G  [SOD523]
J10  PH2.0-4A  [PH200-4A]
J11  HDR200MA-2X3  [HDR200MA-2X3]
J12  HDR254MA-2X20  [HDR254MA-2X20]
R88  22R  [R0402L]
R89  10K  [R0402L]
U6  CH340E  [MSOP-10]

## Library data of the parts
C1 = C-AL-SMD: DSC1: ±20%; DSC2: 10V; DSC3: 低阻抗; DSC4: 2000H; DSC5: -55~105 ℃; DSC6: SMD,5x5.4mm; DSC7: LZ1A101M-CRD54(ST); ID: 4; Manufacture: 先科|立隆|三莹; Part Name: 贴片铝电容; Part Number: C020302140004; Price: 0.12
C2 C13 C15 C17-C19 C30 C31 C33 C43 C47 = C-0603: DSC1: ±20%; DSC2: 10V; DSC3: X5R; ERP Number: 1010200076; ID: 71; Manufacture: 三星|国巨|村田; Part Name: 贴片电容; Part Number: C020102120071; Price: 0.05
C3 C7 C16 C45 C46 = C-0402: DSC1: ±10%; DSC2: 10V; DSC3: X5R; ERP Number: 1010200054; ID: 64; Manufacture: 三星|国巨|村田; Part Name: 贴片电容; Part Number: C020102120064; Price: 0.02
C4 C14 C38 = C-0402: DSC1: ±0.25PF; DSC2: 50V; DSC3: C0G; ERP Number: 1010200056; ID: 18; Manufacture: 三星|国巨|村田; Part Name: 贴片电容; Part Number: C020102120018; Price: 0.01
C5 C6 C9 C10 = C-0603: DSC1: ±20%; DSC2: 6.3V; DSC3: X5R; ERP Number: 1010200133; ID: 72; Manufacture: 三星|国巨|村田; Part Name: 贴片电容; Part Number: C020102120072; Price: 0.06
D1-D3 D6-D29 = DI-ESD: DSC1: 双向; DSC2: Vdc=14V; DSC3: Vbr=300V; DSC4: Vc=30V; DSC5: Cj=0.25pF; ERP Number: 1010800023; ID: 2; Manufacture: AEM; Part Name: ESD; Part Number: C040502250002; Price: 0.06
D4 D5 D30 = DI-XI-S: DSC1: VR=30V; DSC2: IF=200mA; DSC3: VF=350mV/10mA; DSC4: IR=0.5uA; ID: 2; Manufacture: 乐山无线电; Part Name: 肖特基二级管; Part Number: C040202220002; Price: 0.05; Solder: 推荐
H1-H4 = HOLE
J1 = J-MicroUSB_0: DSC1: MicroUSB 5S B TYPE 四脚全插牛角型短针 耐高温; DSC2: 7.6*5.6mm; DSC3: 卧贴; DSC4: U-F-M5DD-Y-L(韩荣); ID: 1; Part Name: USB连接器; Part Number: J060102960001
J2 = RTC-CR1220-2P-SMD: DSC1: CR1220电池座 贴片 双定位柱; DSC3: 贴片; DSC4: CR1220-2; ERP Number: 1040100045; ID: 4; Part Name: 电池座; Part Number: J100303030001
L1 = L-IND: DSC1: ±20%; DSC2: Isat=6.1A; DSC3: Irms=4.3A; DSC4: 48mΩ; DSC5: 4.0*4.0*2.0mm; DSC6: WPN4020H2R2MT(顺络); ERP Number: 1010200404; ID: 20; Manufacture: 顺络; Part Name: 功率电感; Part Number: C060202340020; Price: 0.38
LED1 LED2 = D-LED0603: DSC1: 蓝色LED，SMD,0603，VF=3V; DSC2: NCD0603B1(国星光电); DSC3: 19-217/BHC-ZL1M2RY/3T(亿光); ERP Number: 1010200068; ID: 8; Part Name: LED; Part Number: C140202660004; Price: 0.08
MARK1-MARK4 = MTG240_600_NPH_0: DSC1: 禁止布线层直径=6mm; DSC2: 孔径2.4mm; ID: 11; Type Name: 无铜固定孔
R1 R55 R56 R58-R62 R73-R75 R82 = R-0402: DSC1: ±1%; DSC2: 1/16W; ERP Number: 1010200445; ID: 818; Part Name: 贴片电阻; Part Number: C011002080818; Price: 0.01
R2 R4 R29 R31 R36 R38 = R-0402: DSC1: ±1%; DSC2: 1/16W; ERP Number: 1010200113; ID: 742; Part Name: 贴片电阻; Part Number: C011002080742; Price: 0.01
R3 = R-0402: DSC1: ±1%; DSC2: 1/16W; ERP Number: 1010200139; ID: 1,009; Part Name: 贴片电阻; Part Number: C011002081009; Price: 0.01
R5 = R-0402: DSC1: ±1%; DSC2: 1/16W; ERP Number: 1010200256; ID: 931; Part Name: 贴片电阻; Part Number: C011002080931; Price: 0.01
SW1 = SW-TS4550TP: DSC1: 轻触开关,四脚贴片,立贴; DSC2: SMD,4.5*4.5*5mm; DSC3: TS4550TP(首韩); DSC4: TS-1009S-05026(讯普); ID: 1; Part Name: 轻触开关; Part Number: C180102690001
U1 = U-TLV62569DBVR: DSC1: Vi=2.5-5.5V; DSC2: Vo=0.6-5.5V; DSC3: Io=2A; DSC4: Vfb=0.6V; DSC5: 0.95; DSC6: 1.5MHz; DSC7: 同步降压 轻载效率 低Iq; ID: 3; Manufacture: TI; Part Name: DCDC; Part Number: C070202410003; Price: 0.3; Solder: 推荐
C8 C29 C32 C34 C36 C44 C48 = C-0402: DSC1: ±10%; DSC2: 10V; DSC3: X7R; ID: 60; Manufacture: 三星|国巨|村田; Part Name: 贴片电容; Part Number: C020102120060; Price: 0.01
C11 C12 = C-0402: DSC1: ±5%; DSC2: 50V; DSC3: C0G; ERP Number: 1010200151; ID: 21; Manufacture: 三星|国巨|村田; Part Name: 贴片电容; Part Number: C020102120021; Price: 0.01
J3 = RF-IPEX-20279: DSC1: IPEX-20279-001E-01 板端贴片天线座 U.LF接头; DSC2: 贴片; ID: 1; Part Name: IPEX座; Part Number: J110103040001
L2-L5 = FB-0603: DSC1: 100Ω@100MHz; DSC2: 3A; DSC3: DCR=30mΩ; DSC4: 电源线; ERP Number: 1010200207; ID: 5; Manufacture: 顺络; Part Name: 贴片磁珠; Part Number: C060502370005; Price: 0.03
R6 R12 R14 R42 R52 R54 R80 R81 = R-0402: DSC1: ±1%; DSC2: 1/16W; ID: 413; Part Name: 贴片电阻; Part Number: C011002080413; Price: 0.01
U2 = U-2D01_1
J4 = J-TF-01A: DSC1: TF卡座 自弹式; DSC3: 贴片; DSC4: TF-01A(韩荣); ID: 2; Part Name: SD卡座; Part Number: J080102980002
J5 = J-USB-4AF-DIP-W-3_1: DSC1: USB AF 90度 侧插 铁壳短体10.4 无卷边 白胶; DSC2: 10.4*5.7mm*13.1; DSC3: 通孔弯针; DSC4: C42684(LC); ID: 7; Part Name: USB连接器; Part Number: J060102960007
Q1 = P-MOS: DSC1: Vds=-30V; DSC2: Id=-4.2A; DSC3: Vgs(th)=1.3V; DSC4: Vgs=±12V; DSC5: pd=350mW; ERP Number: 1010800001; ID: 1; Manufacture: 长电; Part Number: C030202190001; Price: 0.17
R7-R9 R21 R89 = R-0402: DSC1: ±1%; DSC2: 1/16W; ERP Number: 1010200140; ID: 856; Part Name: 贴片电阻; Part Number: C011002080856; Price: 0.01
R10 R11 R13 R15-R19 R40 R41 R43-R45 R47-R51 R67-R72 R76-R79 R88 = R-0402: DSC1: ±1%; DSC2: 1/16W; ID: 552; Part Name: 贴片电阻; Part Number: C011002080552; Price: 0.01
R20 = R-0402: DSC1: ±1%; DSC2: 1/16W; ERP Number: 1010200137; ID: 976; Part Name: 贴片电阻; Part Number: C011002080976; Price: 0.01
R22 = R-0402: DSC1: ±1%; DSC2: 1/16W; ERP Number: 1010200334; ID: 837; Part Name: 贴片电阻; Part Number: C011002080837; Price: 0.01
R123 = R-0402: DSC1: ±1%; DSC2: 1/16W; ERP Number: 1010200459; ID: 1,059; Part Name: 贴片电阻; Part Number: C011002081059; Price: 0.01
U3 = U-SY6280AAC: DSC1: 低能耗电源开关; DSC2: 2.4-5.5V 2A; DSC3: 80m?; DSC4: -40~85℃; ERP Number: 1010100222; ID: 1; Manufacture: 矽力杰; Part Name: 功率开关; Part Number: C070402430001; Price: 0.42
C20 C22 C24 C26 = C-0402: DSC1: ±10%; DSC2: 50V; DSC3: X7R; ERP Number: 1010200128; ID: 61; Manufacture: 三星|国巨|村田; Part Name: 贴片电容; Part Number: C020102120061; Price: 0.05
C21 C23 C25 C27 C28 = C-1206: DSC1: ±10%; DSC2: 2KV; DSC3: X7R; ERP Number: 1010200094; ID: 77; Manufacture: 三星|国巨|村田; Part Name: 贴片电容; Part Number: C020102120077; Price: 0.17
C35 C37 = C-0402: DSC1: ±5%; DSC2: 50V; DSC3: C0G; ERP Number: 1010200091; ID: 27; Manufacture: 三星|国巨|村田; Part Name: 贴片电容; Part Number: C020102120027; Price: 0.02
J6 = J-RJ45-1X2: DSC1: RJ45网口连接器,带LED灯,8p8c,横向并排双座,黑色,后脚,4.57,铜壳,无弹片; DSC3: 通孔弯针; ID: 2; Part Number: J120103060002
R23 R25-R27 R30 R33 R34 R37 = R-0402: DSC1: ±1%; DSC2: 1/16W; ID: 453; Part Name: 贴片电阻; Part Number: C011002080453; Price: 0.01
R24 R28 R32 R35 = R-0603: DSC1: ±1%; DSC2: 1/10W; ERP Number: 1010200269; ID: 1,348; Part Name: 贴片电阻; Part Number: C011002081348; Price: 0.01
R39 = R-0805: DSC1: ±1%; DSC2: 1/8W; ERP Number: 1010200447; ID: 1,864; Part Name: 贴片电阻; Part Number: C011002081864; Price: 0.01
R46 = R-0402: DSC1: ±1%; DSC2: 1/16W; ERP Number: 1010200441; ID: 832; Part Name: 贴片电阻; Part Number: C011002080832; Price: 0.01
R53 = R-0402: DSC1: ±1%; DSC2: 1/16W; ERP Number: 1010200470; ID: 1,093; Part Name: 贴片电阻; Part Number: C011002081093; Price: 0.01
R57 = R-0402: DSC1: ±1%; DSC2: 1/16W; ERP Number: 1010200370; ID: 1,055; Part Name: 贴片电阻; Part Number: C011002081055; Price: 0.01
U4 = U-QT24A01_0: DSC1: 贴片 单口千兆或双口百兆; DSC2: 0~70℃; DSC3: SMD,SOP24,15.1*7*4mm; ERP Number: C060702390002; ID: 2; Part Name: 网口变压器
U5 = U-IP101GR: DSC1: Single Port 10/100 MII/RMII/TP/Fiber / Fast Ethernet Transceiver; DSC2: QFN32，5mm×5mm，0.5mm Pitch; DSC3: 0℃~+70℃; ERP Number: 1010100239; ID: 6; Manufacture: IC+(九阳电子); Part Name: 以太网芯片; Part Number: C100102490006; Price: 1.38
XT1 = XTAL-4P: DSC1: 40Ω; DSC2: ±10ppm; DSC3: 12pF; DSC4: -40℃~+85℃; DSC5: 3.2*2.5mm 4P; ID: 6; Manufacture: 泰晶; Part Name: 贴片无源晶振; Part Number: C050102290006; Price: 0.48
J7 = J-FPC05-40P: DSC1: 40P; DSC2: 0.5mm间距; DSC3: 下接 抽拉式 卧贴; DSC4: H=2mm; DSC5: 镀锡; ID: 32; Part Name: FPC座; Part Number: J030105063856
R63-R66 = RN_0402X4: DSC1: ±5%; DSC2: 1/16W; ID: 4; Part Name: 贴片排阻; Part Number: C010302090004; Price: 0.01
C39-C42 = C-0402: DSC1: ±20%; DSC2: 10V; DSC3: X5R; ID: 67; Manufacture: 三星|国巨|村田; Part Name: 贴片电容; Part Number: C020102120067; Price: 0.04
J8 = J-PJ-326A-3P: DSC1: 3.5mm贴片式耳机座 凸头 3P 双定位柱; DSC2: 14*5.6*5.1mm; ID: 11; Part Name: 音频耳机座; Part Number: J050502940003
J9 = J-H-2P: DSC1: 2p; DSC2: 1.25mm间距; DSC3: 通孔180度直针; DSC4: 米黄色胶壳 耐高温; DSC5: A1251WV-2P(CJT); ID: 50; Part Name: MX1.25T; Part Number: J020110233936
R83-R85 = R-0402: DSC1: ±1%; DSC2: 1/16W; ERP Number: 1010200328; ID: 774; Part Name: 贴片电阻; Part Number: C011002080774; Price: 0.01
J10 = J-H-4P: DSC1: 4p; DSC2: 2.0mm间距; DSC3: 通孔180度直针; DSC4: 米黄色胶壳 耐高温; DSC5: A2001WV-4P(CJT); ID: 13; Part Name: PH; Part Number: J020302820003
J11 = J-HDR-D-6: DSC1: 双排单塑; DSC2: 2x3; DSC3: 2mm脚距; DSC4: 通孔直针; DSC5: 针长8.8mm  2.8+2(H塑高)+4 mm; DSC6: 黑胶; DSC7: A2005WV-2x3P(CJT); ID: 2; Part Name: 双排针; Part Number: J010102760002
J12 = J-HDR-D-40: DSC1: 双排单塑; DSC2: 2x20; DSC3: 2.54mm脚距; DSC4: 通孔直针; DSC5: 针长11.5mm 3+2.5(H塑高)+6mm; DSC6: 黑胶; DSC7: A2541WV-2x20P(CJT); ID: 64; Part Name: 双排针; Part Number: J010104013835
U6 = U-CH340E_0: DSC1: USB UART Bridge,Up to 2Mbps; DSC2: MSOP-10，0.5mm Pitch; DSC3: -20℃~+70℃; ERP Number: 1010100113; ID: 17; Manufacture: WCH(南京沁恒); Part Name: USB芯片; Part Number: C100202500006; Price: 2.19

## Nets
GND: C1.2 C2.1 C3.1 C5.1 C6.1 C7.1 C8.1 C9.1 C10.1 C11.1 C12.1 C13.1 C14.1 C15.1 C17.1 C18.1 C19.1 C20.2 C22.2 C24.2 C26.2 C28.1 C29.1 C30.1 C31.1 C32.1 C33.1 C34.1 C35.1 C36.1 C37.1 C38.1 C41.1 C42.1 C43.1 C44.1 C47.1 C48.1 D1.2(I/O1) D2.2(I/O1) D3.2(I/O1) D6.2(I/O1) D7.2(I/O1) D8.2(I/O1) D9.2(I/O1) D10.2(I/O1) D11.2(I/O1) D12.2(I/O1) D13.2(I/O1) D14.2(I/O1) D15.2(I/O1) D16.2(I/O1) D21.2(I/O1) D22.2(I/O1) D23.2(I/O1) D24.2(I/O1) D25.2(I/O1) D26.2(I/O1) D28.2(I/O1) D29.2(I/O1) J1.5(GND) J2.2(-) J3.1(GND1) J3.3(GND2) J3.4(GND3) J4.6(VSS) J4.10(G1) J4.11(G2) J4.12(G3) J4.13(G4) J5.4(GND1) J6.A9(ALEDY-) J6.B9(BLEDY-) J6.B11(BLEDG-) J7.1 J7.2 J7.8 J7.15 J7.21 J7.23 J7.26 J7.28 J7.30 J7.32 J7.41 J7.42 J8.1(COM) J10.2 J12.6 J12.9 J12.14 J12.20 J12.25 J12.30 J12.34 J12.39 LED2.C(CATHODE) R5.2 R22.2 R39.1 R46.2 R56.1 R58.1 R62.2 R85.2 R123.2 U1.2(GND) U2.2(GND1) U2.4(GND2) U2.35(GND3) U2.42(GND4) U2.53(GND5) U2.66(GND6) U2.80(GND7) U2.85(GND8) U2.90(GND9) U2.95(GND10) U3.2(GND) U5.33(EPad) U6.3(GND) XT1.2 XT1.4
GND_EARTH: C21.1 C23.1 C25.1 C27.1 C28.2 H1.1 H2.1 H3.1 H4.1 J1.6(FG2) J1.7(FG3) J1.8(FG4) J1.9(FG5) J5.5(GND2) J5.6(GND3) J5.7(GND4) J6.FG1 J6.FG2 R39.2
VCC5V: C1.1 C2.2 C3.2 C19.2 C47.2 J1.1(VCC) J7.39 J7.40 J12.2 J12.4 U1.1(EN) U1.4(VIN) U3.5(IN) U6.7(VCC)
VCC_RTC: C7.2 D4.C D5.C U2.96(AVDD_RTC)
50MHz_CLKOUT: R52.2 U5.10(TxClk/50MClki) U5.14(RxClk/50M_Clko)
AUD_LINEOUT_L0: R80.1 U2.92(AUD_LINEOUT_L0)
AUD_LINEOUT_R0: R81.1 U2.91(AUD_LINEOUT_R0)
AUD_MIC+: C45.1 D27.2(I/O1) J9.1 R83.2 R84.1
AUD_MIC-: C46.1 D27.1(I/O2) J9.2 R84.2 R85.1
AUD_MICCM0: C46.2 U2.93(AUD_MICCM0)
AUD_MICIN0: C45.2 U2.94(AUD_MICIN0)
CRS: R56.2 U5.20(CRS/LEDMod)
DM_P1: U2.86(DM_P1)
DM_P2: R12.1 U2.89(DM_P2)
DM_P2_: D15.1(I/O2) J5.2(D-) R12.2
DMIC_CLK: J12.40 U2.20(DMIC_CLK)
DMIC_L: J12.38 U2.19(DMIC_L)
DMIC_R: J12.36 U2.18(DMIC_R)
DP_P1: U2.87(DP_P1)
DP_P2: R14.1 U2.88(DP_P2)
DP_P2_: D14.1(I/O2) J5.3(D+) R14.2
ET_RX_ER-E: R59.2 U5.21(RxEr/Int32)
ETH_RN: R27.1 U2.81(ETH_RN)
ETH_RP: R26.1 U2.82(ETH_RP)
ETH_RXN: D18.2(I/O1) R27.2 U4.6(TD2-)
ETH_RXP: D18.1(I/O2) R26.2 U4.5(TD2+)
ETH_TN: R25.1 U2.83(ETH_TN)
ETH_TP: R23.1 U2.84(ETH_TP)
ETH_TXN: D17.2(I/O1) R25.2 U4.3(TD1-)
ETH_TXP: D17.1(I/O2) R23.2 U4.2(TD1+)
ETH_XI: C35.2 R53.1 U5.2(Xi) XT1.1
ETH_XO: R54.2 U5.3(Xo)
FUART_CTS: J12.33 U2.33(FUART_CTS)
FUART_RTS: J12.35 U2.34(FUART_RTS)
FUART_RX: J12.31 U2.31(FUART_RX)
FUART_TX: J12.29 U2.32(FUART_TX)
GPIO0/RMII_MDIO: R40.1 U2.74(GPIO0)
GPIO1/RMII_MDC: R41.1 U2.75(GPIO1)
GPIO2/I2C1_SCL: R77.1 U2.76(GPIO2/I2C1_SCL)
GPIO3/I2C1_SDA: R76.1 U2.77(GPIO3/I2C1_SDA)
GPIO4/PWM0: R70.1 U2.5(GPIO4/PWM0)
GPIO5/PWM1: J12.26 U2.6(GPIO5/PWM1)
GPIO6/I2C0_SCL: J12.5 U2.7(GPIO6/I2C0_SCL)
GPIO7/I2C0_SDA: J12.3 U2.8(GPIO7/I2C0_SDA)
GPIO8/UART2_RX/SPI0_CZ: J12.24 U2.9(GPIO8/UART2_RX/SPI0_CZ)
GPIO9/UART2_TX/SPI0_CK: J12.23 U2.10(GPIO9/UART2_TX/SPI0_CK)
GPIO10/SPI0_DI: J12.21 U2.11(GPIO10/SPI0_DI)
GPIO11/SPI0_DO: J12.19 U2.12(GPIO11/SPI0_DO)
GPIO12: J12.11 R79.1 U2.13(GPIO12)
GPIO13: J12.7 R78.1 U2.14(GPIO13)
GPIO14: R19.1 U2.15(GPIO14)
GPIO47: J12.13 U2.27(GPIO47)
GPIO48: J12.15 U2.28(GPIO48)
GPIO85: LED1.C(CATHODE) U2.16(GPIO85)
GPIO86: R71.1 U2.17(GPIO86)
GPIO90: R21.1 U2.21(GPIO90)
INTn: D21.1(I/O2) J7.34 R78.2
LAN0-R+: J6.B3 U4.20(MX2+)
LAN0-R-: J6.B6 U4.19(MX2-)
LAN0-T+: J6.B1 U4.23(MX1+)
LAN0-T-: J6.B2 U4.22(MX1-)
LAN1-R+: J6.A3 U4.14(MX4+)
LAN1-R-: J6.A6 U4.13(MX4-)
LAN1-T+: J6.A1 U4.17(MX3+)
LAN1-T-: J6.A2 U4.16(MX3-)
LCD_PWM: J7.29 R70.2
LCD_RSTB: J7.31 R71.2
LED0/PHYAD0: R38.2 R61.2 U5.11(LED0/PhyAD0)
LED3/PHYAD3: R36.2 R62.1 U5.12(LED3/PhyAD3)
LINEOUTL-: C39.2 C42.2 R80.2
LINEOUTL_: C39.1 D26.1(I/O2) J8.3(R)
LINEOUTR-: C40.2 C41.2 R81.2
LINEOUTR_: C40.1 D25.1(I/O2) J8.2(L)
MDI_RN: R37.1 U5.26(MDiRn)
MDI_RP: R34.1 U5.27(MDiRp)
MDI_RXN: D20.2(I/O1) R37.2 U4.12(TD4-)
MDI_RXP: D20.1(I/O2) R34.2 U4.11(TD4+)
MDI_TN: R33.1 U5.29(MDiTn)
MDI_TP: R30.1 U5.30(MDiTp)
MDI_TXN: D19.2(I/O1) R33.2 U4.9(TD3-)
MDI_TXP: D19.1(I/O2) R30.2 U4.8(TD3+)
nSD_CD: D12.1(I/O2) J4.9(CD) R9.2 R17.2
Panel_B3: J7.16 R64.8
Panel_B4: J7.17 R66.5
Panel_B5: J7.18 R66.6
Panel_B6: J7.19 R66.7
Panel_B7: J7.20 R66.8
Panel_DCLK: C38.2 J7.22 R72.2
Panel_DE: J7.27 R69.2
Panel_G2: J7.9 R65.6
Panel_G3: J7.10 R65.7
Panel_G4: J7.11 R65.8
Panel_G5: J7.12 R64.5
Panel_G6: J7.13 R64.6
Panel_G7: J7.14 R64.7
Panel_HS: J7.24 R67.2
Panel_R3: J7.3 R63.5
Panel_R4: J7.4 R63.6
Panel_R5: J7.5 R63.7
Panel_R6: J7.6 R63.8
Panel_R7: J7.7 R65.5
Panel_VS: J7.25 R68.2
PHY_AVDD33: C33.2 C34.2 L5.2 U5.31(AVD33)
PHY_DVDD33: C31.2 C32.2 L4.2 R55.1 R59.1 R60.1 U5.13(IOVDD)
PM_IRIN: J12.37 U2.23(PM_IRIN)
PM_LED0: R31.1 U2.78(PM_LED0)
PM_LED0_: J6.B12(BLEDG+) R31.2
PM_LED1: R29.1 U2.79(PM_LED1)
PM_LED1_: J6.B10(BLEDY+) R29.2
PM_RESET: D3.1(I/O2) SW1.3 U2.24(PM_RESET)
PM_UART_RX: J11.4 U2.25(PM_UART_RX)
PM_UART_TX: J11.3 U2.26(PM_UART_TX)
REGOUT: R42.1 U5.28(RegOut)
RMII_COL: R55.2 U5.4(Col/RMII)
RMII_MDC: R41.2 U5.22(MDC)
RMII_MDIO: R40.2 R60.2 U5.23(MDIO)
RMII_REF_CLK: R47.2 R52.1
RMII_RST: C36.2 R51.2 R57.2 U5.32(nRst)
RMII_RX_D0: R44.2 U5.18(RxD0)
RMII_RX_D1: R45.2 U5.17(RxD1)
RMII_RX_DV: R43.2 R58.2 U5.19(RxDV/CRS_DV)
RMII_TX_D0: R48.2 U5.9(TxD0)
RMII_TX_D1: R49.2 U5.8(TxD1)
RMII_TX_EN: R50.2 U5.5(TxEn)
RST#: D22.1(I/O2) J7.33 R73.2 R79.2
RTC_VBAT: D5.A J2.1(+)
SAR_GPIO2: J12.32 U2.22(SAR_GPIO2)
SD_CDZ: R17.1 U2.67(SD_CDZ)
SD_CLK: R18.1 U2.70(SD_CLK)
SD_CLK_: C14.2 D13.1(I/O2) J4.5(CLK) R18.2
SD_CMD: R16.1 U2.71(SD_CMD)
SD_CMD_: D11.1(I/O2) J4.3(CMD) R8.2 R16.2
SD_D0: R10.1 U2.69(SD_D0)
SD_D0_: D7.1(I/O2) J4.7(DATA0) R7.2 R10.2
SD_D1: R11.1 U2.68(SD_D1)
SD_D1_: D8.1(I/O2) J4.8(DATA1) R11.2
SD_D2: R13.1 U2.73(SD_D2)
SD_D2_: D9.1(I/O2) J4.1(DATA2) R13.2
SD_D3: R15.1 U2.72(SD_D3)
SD_D3_: D10.1(I/O2) J4.2(CD/DATA3) R15.2
SOM_3V3: C8.2 C9.2 C10.2 L2.2 U2.1(SYS_3V3)
SYS_3V3: C4.2 C5.2 C6.2 C15.2 C16.2 D4.A J6.A12(ALEDG+) J7.37 J7.38 J12.1 J12.17 L1.2 L2.1 L4.1 L5.1 Q1.2(SOURCE) R1.1 R2.1 R3.1 R4.1 R7.1 R8.1 R9.1 R20.1 R57.1 R61.1 R73.1 R74.1 R75.1 R82.1 R89.1
TF_3V3: C17.2 L3.1 Q1.3(DRAIN)
TP_SCL: D23.1(I/O2) J7.36 R74.2 R77.2
TP_SDA: D24.1(I/O2) J7.35 R75.2 R76.2
TTL0: R63.4 U2.36(TTL0)
TTL1: R63.3 U2.37(TTL1)
TTL2: R63.2 U2.38(TTL2)
TTL3: R63.1 U2.39(TTL3)
TTL4: R65.4 U2.40(TTL4)
TTL5: R65.3 U2.41(TTL5)
TTL6/MIPI_TX_D0P: R65.2 U2.43(TTL6/MIPI_TX_D0P)
TTL7/MIPI_TX_D0N: R65.1 U2.44(TTL7/MIPI_TX_D0N)
TTL8/MIPI_TX_D1P: R64.4 U2.45(TTL8/MIPI_TX_D1P)
TTL9/MIPI_TX_D1N: R64.3 U2.46(TTL9/MIPI_TX_D1N)
TTL10/MIPI_TX_CKP: R64.2 U2.47(TTL10/MIPI_TX_CKP)
TTL11/MIPI_TX_CKN: R64.1 U2.48(TTL11/MIPI_TX_CKN)
TTL12/MIPI_TX_D2P: R66.4 U2.49(TTL12/MIPI_TX_D2P)
TTL13/MIPI_TX_D2N: R66.3 U2.50(TTL13/MIPI_TX_D2N)
TTL14/MIPI_TX_D3P: R66.2 U2.51(TTL14/MIPI_TX_D3P)
TTL15/MIPI_TX_D3N: R66.1 U2.52(TTL15/MIPI_TX_D3N)
TTL16: R51.1 U2.54(TTL16)
TTL17: R49.1 U2.55(TTL17)
TTL18: R48.1 U2.56(TTL18)
TTL19: R50.1 U2.57(TTL19)
TTL20: R47.1 U2.58(TTL20)
TTL21: R43.1 U2.59(TTL21)
TTL22: R44.1 U2.60(TTL22)
TTL23: R45.1 U2.61(TTL23)
TTL24/LCD_PCLK: R72.1 U2.62(TTL24)
TTL25/LCD_HSYNC: R67.1 U2.63(TTL25)
TTL26/LCD_VSYNC: R68.1 U2.64(TTL26)
TTL27/LCD_DE: R69.1 U2.65(TTL27)
UART0_RX: D30.A J11.2 R89.2
UART0_RX_: D29.1(I/O2) J10.3 J11.6
UART0_TX: J11.1 R88.1
UART0_TX_: D28.1(I/O2) J10.4 J11.5
UART1_RX: J12.18 U2.29(UART1_RX)
UART1_TX: J12.16 U2.30(UART1_TX)
UD+: D2.1(I/O2) J1.3(D+) U6.1(UD+)
UD-: D1.1(I/O2) J1.2(D-) U6.2(UD-)
USB-DRVVBUS: R19.2 R123.1 U3.4(EN)
USB_VBUS: C18.2 D16.1(I/O2) J5.1(VBUS) U3.1(VOUT)
WIFI_ANT: C11.2 R6.1 U2.3(WF_ANT)
WIFI_ANT_: C12.2 D6.1(I/O2) J3.2(SIG) R6.2
N992055: C13.2 J4.4(VDD) L3.2
N1029238: L1.1 U1.3(SW)
N1029242: C4.1 R3.2 R5.1 U1.5(FB)
N1030799: C16.1 Q1.1(GATE) R20.2 R21.2
N6892349: R22.1 U3.3(OCB)
N11463456: LED2.A(ANODE) R4.2
N11537825: C43.2 C44.2 R82.2 R83.1
N11641260: LED1.A(ANODE) R2.2
N11726744: J6.A4 J6.A5
N11726756: J6.A7 J6.A8
N11730332: C29.2 C30.2 R42.2
N11730936: R46.1 U5.25(Iset)
N11731046: C37.2 R53.2 R54.1 XT1.3
N11735014: R28.1 U4.21(MCT2)
N11735018: C23.2 R28.2
N11735022: C21.2 R24.2
N11735030: R24.1 U4.24(MCT1)
N11735054: R32.1 U4.18(MCT3)
N11735058: C25.2 R32.2
N11735062: C27.2 R35.2
N11735070: R35.1 U4.15(MCT4)
N11735786: C20.1 U4.1(TCT1)
N11735790: C22.1 U4.4(TCT2)
N11735890: C24.1 U4.7(TCT3)
N11735894: C26.1 U4.10(TCT4)
N11746324: J6.B4 J6.B5
N11746339: J6.B7 J6.B8
N11786183: C48.2 U6.10(V3)
N11786289: R88.2 U6.9(RXD)
N11786293: D30.C U6.8(TXD)
N11791074: R1.2 SW1.1
N11830519: J6.A10(ALEDY+) R36.1
N11830523: J6.A11(ALEDG-) R38.1

Not connected (* = marked no-connect by the designer): J1 4(ID)*; J6 NC1* NC2*; J10 1; J12 8 10 12 22 27 28; MARK1 1; MARK2 1; MARK3 1; MARK4 1; SW1 2 4; U5 1(TxEr/FxSD)* 6(TxD3)* 7(TxD2)* 15(RxD3)* 16(RxD2)* 24(TestOn)*; U6 4(RTS#)* 5(CTS#)* 6(TNOW)*

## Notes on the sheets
sheet 3
- AUD_LINEOUT
- AUDIO
- DMIC
- 3.5mm耳机座
- USB1
- AUD_MIC
- AUD_LINEOUT
- UART
- 调试接口
- USB2
- USB2.0
- PM_UART
- USB2.0 HOST
- PM_UART
- PH2-4
- SDIO
- TFCARD
- 2D01
- GPIO X 20
- 扩展接口
- GPIO
- GPIO
- 2 x 20P
- PWM
- FUART
- UART1
- UART2
- I2C X 2
- ETH1
- RMII
- RGB565
- RMII
- RGB565
- RJ45 X 2
- IP101
- FPC-40PIN
- I2C1
sheet 4
- SYS_3V3
sheet 7
- LINE OUT
sheet 8
- LCD
- 22R电阻靠近主控
- TP
- 22R电阻靠近主控
sheet 9
- TF_CARD
